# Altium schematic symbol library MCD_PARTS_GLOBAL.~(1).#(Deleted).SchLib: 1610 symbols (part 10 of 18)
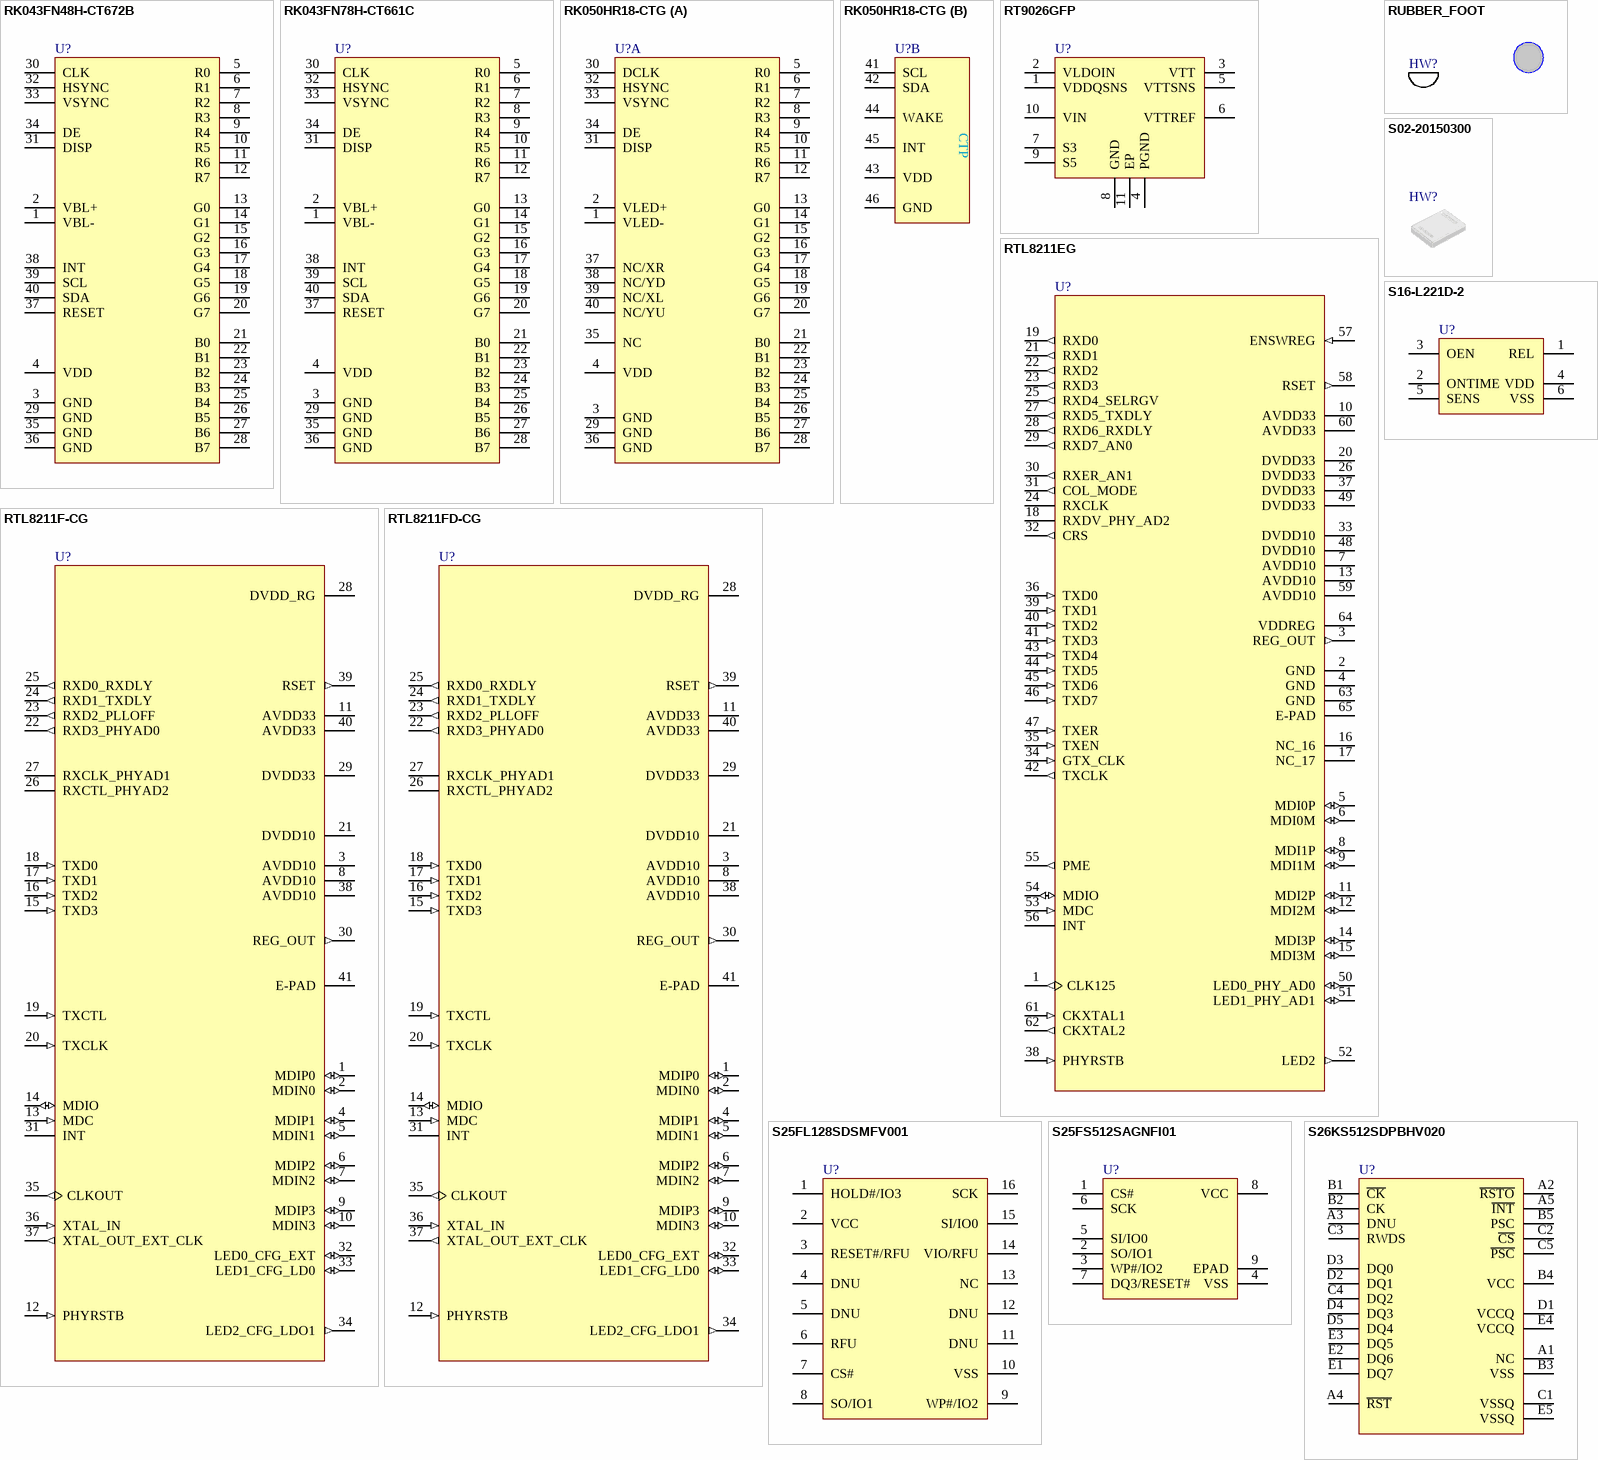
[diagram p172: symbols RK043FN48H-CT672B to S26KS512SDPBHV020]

## RTL8211F-CG
designator U?
pins: 1 MDIP0 (io), 2 MDIN0 (io), 3 AVDD10 (power), 4 MDIP1 (io), 5 MDIN1 (io), 6 MDIP2 (io), 7 MDIN2 (io), 8 AVDD10 (power), 9 MDIP3 (io), 10 MDIN3 (io), 11 AVDD33 (power), 12 PHYRSTB (in), 13 MDC (in), 14 MDIO (io), 15 TXD3 (in), 16 TXD2 (in), 17 TXD1 (in), 18 TXD0 (in), 19 TXCTL (in), 20 TXCLK (in), 21 DVDD10 (power), 22 RXD3_PHYAD0 (out), 23 RXD2_PLLOFF (out), 24 RXD1_TXDLY (out), 25 RXD0_RXDLY (out), 26 RXCTL_PHYAD2, 27 RXCLK_PHYAD1, 28 DVDD_RG (power), 29 DVDD33 (power), 30 REG_OUT (out), 31 INT, 32 LED0_CFG_EXT (io), 33 LED1_CFG_LD0 (io), 34 LED2_CFG_LDO1 (out), 35 CLKOUT (out), 36 XTAL_IN (in), 37 XTAL_OUT_EXT_CLK (out), 38 AVDD10 (power), 39 RSET (out), 40 AVDD33 (power), 41 E-PAD (power)

## RTL8211FD-CG
designator U?
pins: 1 MDIP0 (io), 2 MDIN0 (io), 3 AVDD10 (power), 4 MDIP1 (io), 5 MDIN1 (io), 6 MDIP2 (io), 7 MDIN2 (io), 8 AVDD10 (power), 9 MDIP3 (io), 10 MDIN3 (io), 11 AVDD33 (power), 12 PHYRSTB (in), 13 MDC (in), 14 MDIO (io), 15 TXD3 (in), 16 TXD2 (in), 17 TXD1 (in), 18 TXD0 (in), 19 TXCTL (in), 20 TXCLK (in), 21 DVDD10 (power), 22 RXD3_PHYAD0 (out), 23 RXD2_PLLOFF (out), 24 RXD1_TXDLY (out), 25 RXD0_RXDLY (out), 26 RXCTL_PHYAD2, 27 RXCLK_PHYAD1, 28 DVDD_RG (power), 29 DVDD33 (power), 30 REG_OUT (out), 31 INT, 32 LED0_CFG_EXT (io), 33 LED1_CFG_LD0 (io), 34 LED2_CFG_LDO1 (out), 35 CLKOUT (out), 36 XTAL_IN (in), 37 XTAL_OUT_EXT_CLK (out), 38 AVDD10 (power), 39 RSET (out), 40 AVDD33 (power), 41 E-PAD (power)

## RUBBER_FOOT
designator HW?

## S02-20150300
designator HW?

## S16-L221D-2
designator U?
pins: 1 REL, 2 ONTIME, 3 OEN, 4 VDD, 5 SENS, 6 VSS

## S25FL128SDSMFV001
designator U?
pins: 1 HOLD#/IO3, 2 VCC, 3 RESET#/RFU, 4 DNU, 5 DNU, 6 RFU, 7 CS#, 8 SO/IO1, 9 WP#/IO2, 10 VSS, 11 DNU, 12 DNU, 13 NC, 14 VIO/RFU, 15 SI/IO0, 16 SCK

## S25FS512SAGNFI01
designator U?
pins: 1 CS#, 2 SO/IO1, 3 WP#/IO2, 4 VSS, 5 SI/IO0, 6 SCK, 7 DQ3/RESET#, 8 VCC, 9 EPAD

## S26KS512SDPBHV020
designator U?
pins: A1 NC, A2 ~{RSTO}, A3 DNU, A4 ~{RST}, A5 ~{INT}, B1 ~{CK}, B2 CK, B3 VSS, B4 VCC, B5 PSC, C1 VSSQ, C2 ~{CS}, C3 RWDS, C4 DQ2, C5 ~{PSC}, D1 VCCQ, D2 DQ1, D3 DQ0, D4 DQ3, D5 DQ4, E1 DQ7, E2 DQ6, E3 DQ5, E4 VCCQ, E5 VSSQ

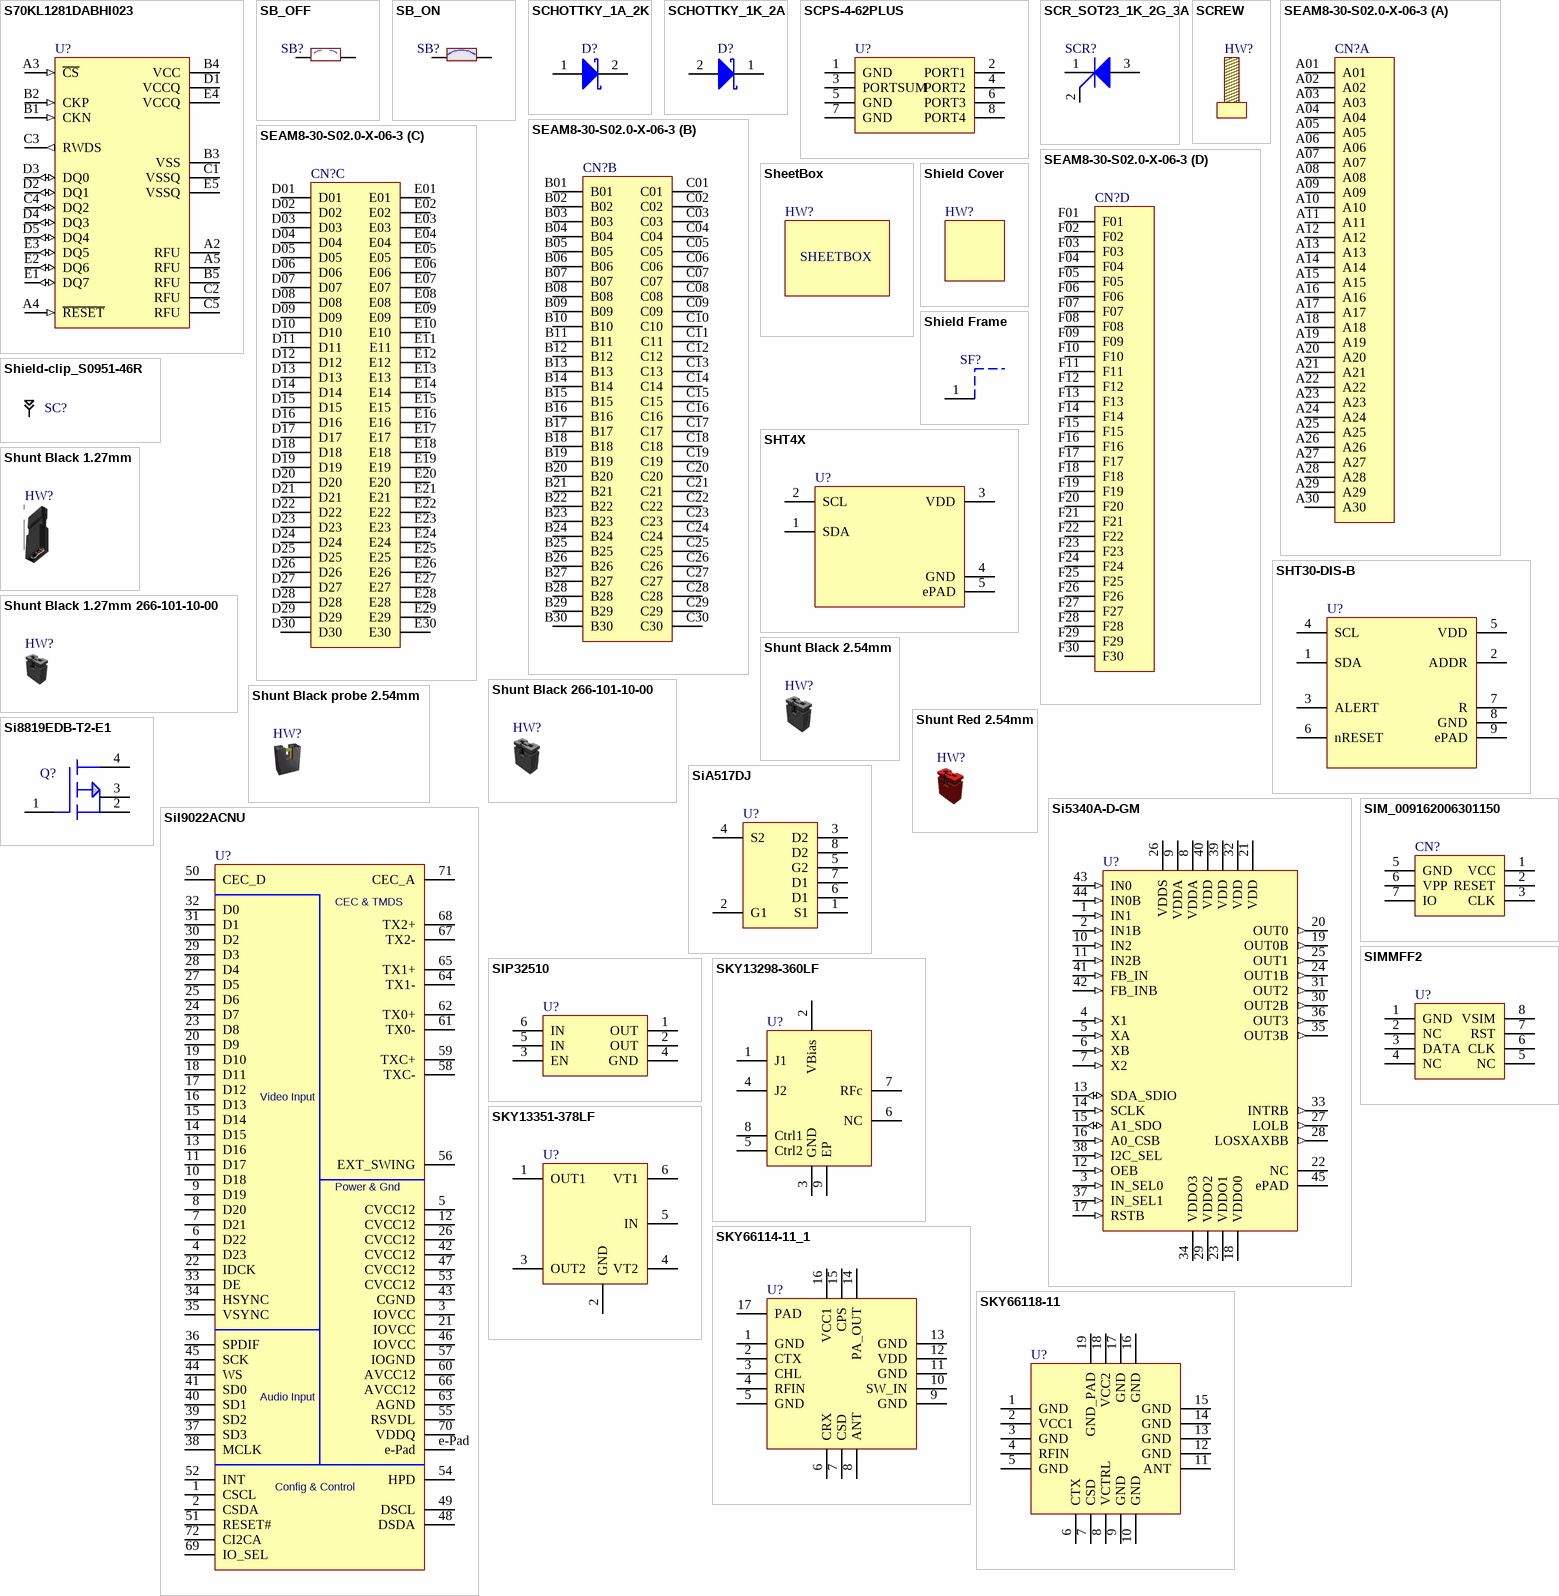
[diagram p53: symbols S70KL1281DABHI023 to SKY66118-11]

## S70KL1281DABHI023
designator U?
pins: A2 RFU (power), A3 ~{CS} (in), A4 ~{RESET} (in), A5 RFU (power), B1 CKN (in), B2 CKP (in), B3 VSS (power), B4 VCC (power), B5 RFU (power), C1 VSSQ (power), C2 RFU (power), C3 RWDS (out), C4 DQ2 (io), C5 RFU (power), D1 VCCQ (power), D2 DQ1 (io), D3 DQ0 (io), D4 DQ3 (io), D5 DQ4 (io), E1 DQ7 (io), E2 DQ6 (io), E3 DQ5 (io), E4 VCCQ (power), E5 VSSQ (power)

## SB_OFF
designator SB?
pins: 1, 2

## SB_ON
designator SB?
pins: 1, 2

## SCHOTTKY_1A_2K
designator D?
pins: 1 A, 2 K

## SCHOTTKY_1K_2A
designator D?
pins: 1 K, 2 A

## SCPS-4-62PLUS
designator U?
pins: 1 GND, 2 PORT1, 3 PORTSUM, 4 PORT2, 5 GND, 6 PORT3, 7 GND, 8 PORT4

## SCR_SOT23_1K_2G_3A
designator SCR?
pins: 1 K, 2 G, 3 A

## SCREW
designator HW?  (mechanical)

## SEAM8-30-S02.0-X-06-3
designator CN?
part A pins: A01, A02, A03, A04, A05, A06, A07, A08, A09, A10, A11, A12, A13, A14, A15, A16, A17, A18, A19, A20, A21, A22, A23, A24, A25, A26, A27, A28, A29, A30
part B pins: B01, B02, B03, B04, B05, B06, B07, B08, B09, B10, B11, B12, B13, B14, B15, B16, B17, B18, B19, B20, B21, B22, B23, B24, B25, B26, B27, B28, B29, B30, C01, C02, C03, C04, C05, C06, C07, C08, C09, C10, C11, C12, C13, C14, C15, C16, C17, C18, C19, C20, C21, C22, C23, C24, C25, C26, C27, C28, C29, C30
part C pins: D01, D02, D03, D04, D05, D06, D07, D08, D09, D10, D11, D12, D13, D14, D15, D16, D17, D18, D19, D20, D21, D22, D23, D24, D25, D26, D27, D28, D29, D30, E01, E02, E03, E04, E05, E06, E07, E08, E09, E10, E11, E12, E13, E14, E15, E16, E17, E18, E19, E20, E21, E22, E23, E24, E25, E26, E27, E28, E29, E30
part D pins: F01, F02, F03, F04, F05, F06, F07, F08, F09, F10, F11, F12, F13, F14, F15, F16, F17, F18, F19, F20, F21, F22, F23, F24, F25, F26, F27, F28, F29, F30

## SheetBox
designator HW?  (no BOM)

## Shield Cover
designator HW?

## Shield Frame
designator SF?
pins: 1

## Shield-clip_S0951-46R
designator SC?
pins: 1

## SHT4X
designator U?
pins: 1 SDA, 2 SCL, 3 VDD, 4 GND, 5 ePAD

## SHT30-DIS-B
designator U?
pins: 1 SDA, 2 ADDR, 3 ALERT, 4 SCL, 5 VDD, 6 nRESET, 7 R, 8 GND, 9 ePAD

## Shunt Black 1.27mm
designator HW?  (mechanical)

## Shunt Black 1.27mm 266-101-10-00
designator HW?  (mechanical)

## Shunt Black 2.54mm
designator HW?  (mechanical)

## Shunt Black 266-101-10-00
designator HW?  (mechanical)

## Shunt Black probe 2.54mm
designator HW?  (mechanical)

## Shunt Red 2.54mm
designator HW?  (mechanical)

## Si5340A-D-GM
designator U?
pins: 1 IN1 (in), 2 IN1B (in), 3 IN_SEL0 (in), 4 X1 (in), 5 XA (in), 6 XB (in), 7 X2 (in), 8 VDDA (power), 9 VDDA (power), 10 IN2 (in), 11 IN2B (in), 12 OEB (in), 13 SDA_SDIO (io), 14 SCLK (in), 15 A1_SDO (io), 16 A0_CSB (in), 17 RSTB (in), 18 VDDO0 (power), 19 OUT0B (out), 20 OUT0 (out), 21 VDD (power), 22 NC, 23 VDDO1 (power), 24 OUT1B (out), 25 OUT1 (out), 26 VDDS (power), 27 LOLB (out), 28 LOSXAXBB (out), 29 VDDO2 (power), 30 OUT2B (out), 31 OUT2 (out), 32 VDD (power), 33 INTRB (out), 34 VDDO3 (power), 35 OUT3B (out), 36 OUT3 (out), 37 IN_SEL1 (in), 38 I2C_SEL (in), 39 VDD (power), 40 VDD (power), 41 FB_IN (in), 42 FB_INB (in), 43 IN0 (in), 44 IN0B (in), 45 ePAD (power)

## Si8819EDB-T2-E1
designator Q?
pins: 1 G, 2 S, 3 S, 4 D

## SiA517DJ
designator U?
pins: 1 S1, 2 G1, 3 D2, 4 S2, 5 G2, 6 D1, 7 D1, 8 D2

## SiI9022ACNU
designator U?
pins: 1 CSCL, 2 CSDA, 3 IOVCC (power), 4 D23, 5 CVCC12 (power), 6 D22, 7 D21, 8 D20, 9 D19, 10 D18, 11 D17, 12 CVCC12 (power), 13 D16, 14 D15, 15 D14, 16 D13, 17 D12, 18 D11, 19 D10, 20 D9, 21 IOVCC (power), 22 IDCK, 23 D8, 24 D7, 25 D6, 26 CVCC12 (power), 27 D5, 28 D4, 29 D3, 30 D2, 31 D1, 32 D0, 33 DE, 34 HSYNC, 35 VSYNC, 36 SPDIF, 37 SD3, 38 MCLK, 39 SD2, 40 SD1, 41 SD0, 42 CVCC12 (power), 43 CGND (power), 44 WS, 45 SCK, 46 IOVCC (power), 47 CVCC12 (power), 48 DSDA, 49 DSCL, 50 CEC_D, 51 RESET#, 52 INT, 53 CVCC12 (power), 54 HPD, 55 RSVDL (power), 56 EXT_SWING, 57 IOGND (power), 58 TXC-, 59 TXC+, 60 AVCC12 (power), 61 TX0-, 62 TX0+, 63 AGND (power), 64 TX1-, 65 TX1+, 66 AVCC12 (power), 67 TX2-, 68 TX2+, 69 IO_SEL, 70 VDDQ (power), 71 CEC_A, 72 CI2CA, e-Pad (power)

## SIM_009162006301150
designator CN?
pins: 1 VCC, 2 RESET, 3 CLK, 5 GND, 6 VPP, 7 IO

## SIMMFF2
designator U?
pins: 1 GND, 2 NC, 3 DATA, 4 NC, 5 NC, 6 CLK, 7 RST, 8 VSIM

## SIP32510
designator U?
pins: 1 OUT, 2 OUT, 3 EN, 4 GND, 5 IN, 6 IN

## SKY13298-360LF
designator U?
pins: 1 J1, 2 VBias, 3 GND, 4 J2, 5 Ctrl2, 6 NC, 7 RFc, 8 Ctrl1, 9 EP

## SKY13351-378LF
designator U?
pins: 1 OUT1, 2 GND, 3 OUT2, 4 VT2, 5 IN, 6 VT1

## SKY66114-11_1
designator U?
pins: 1 GND, 2 CTX, 3 CHL, 4 RFIN, 5 GND, 6 CRX, 7 CSD, 8 ANT, 9 GND, 10 SW_IN, 11 GND, 12 VDD, 13 GND, 14 PA_OUT, 15 CPS, 16 VCC1, 17 PAD

## SKY66118-11
designator U?
pins: 1 GND, 2 VCC1, 3 GND, 4 RFIN, 5 GND, 6 CTX, 7 CSD, 8 VCTRL, 9 GND, 10 GND, 11 ANT, 12 GND, 13 GND, 14 GND, 15 GND, 16 GND, 17 GND, 18 VCC2, 19 GND_PAD

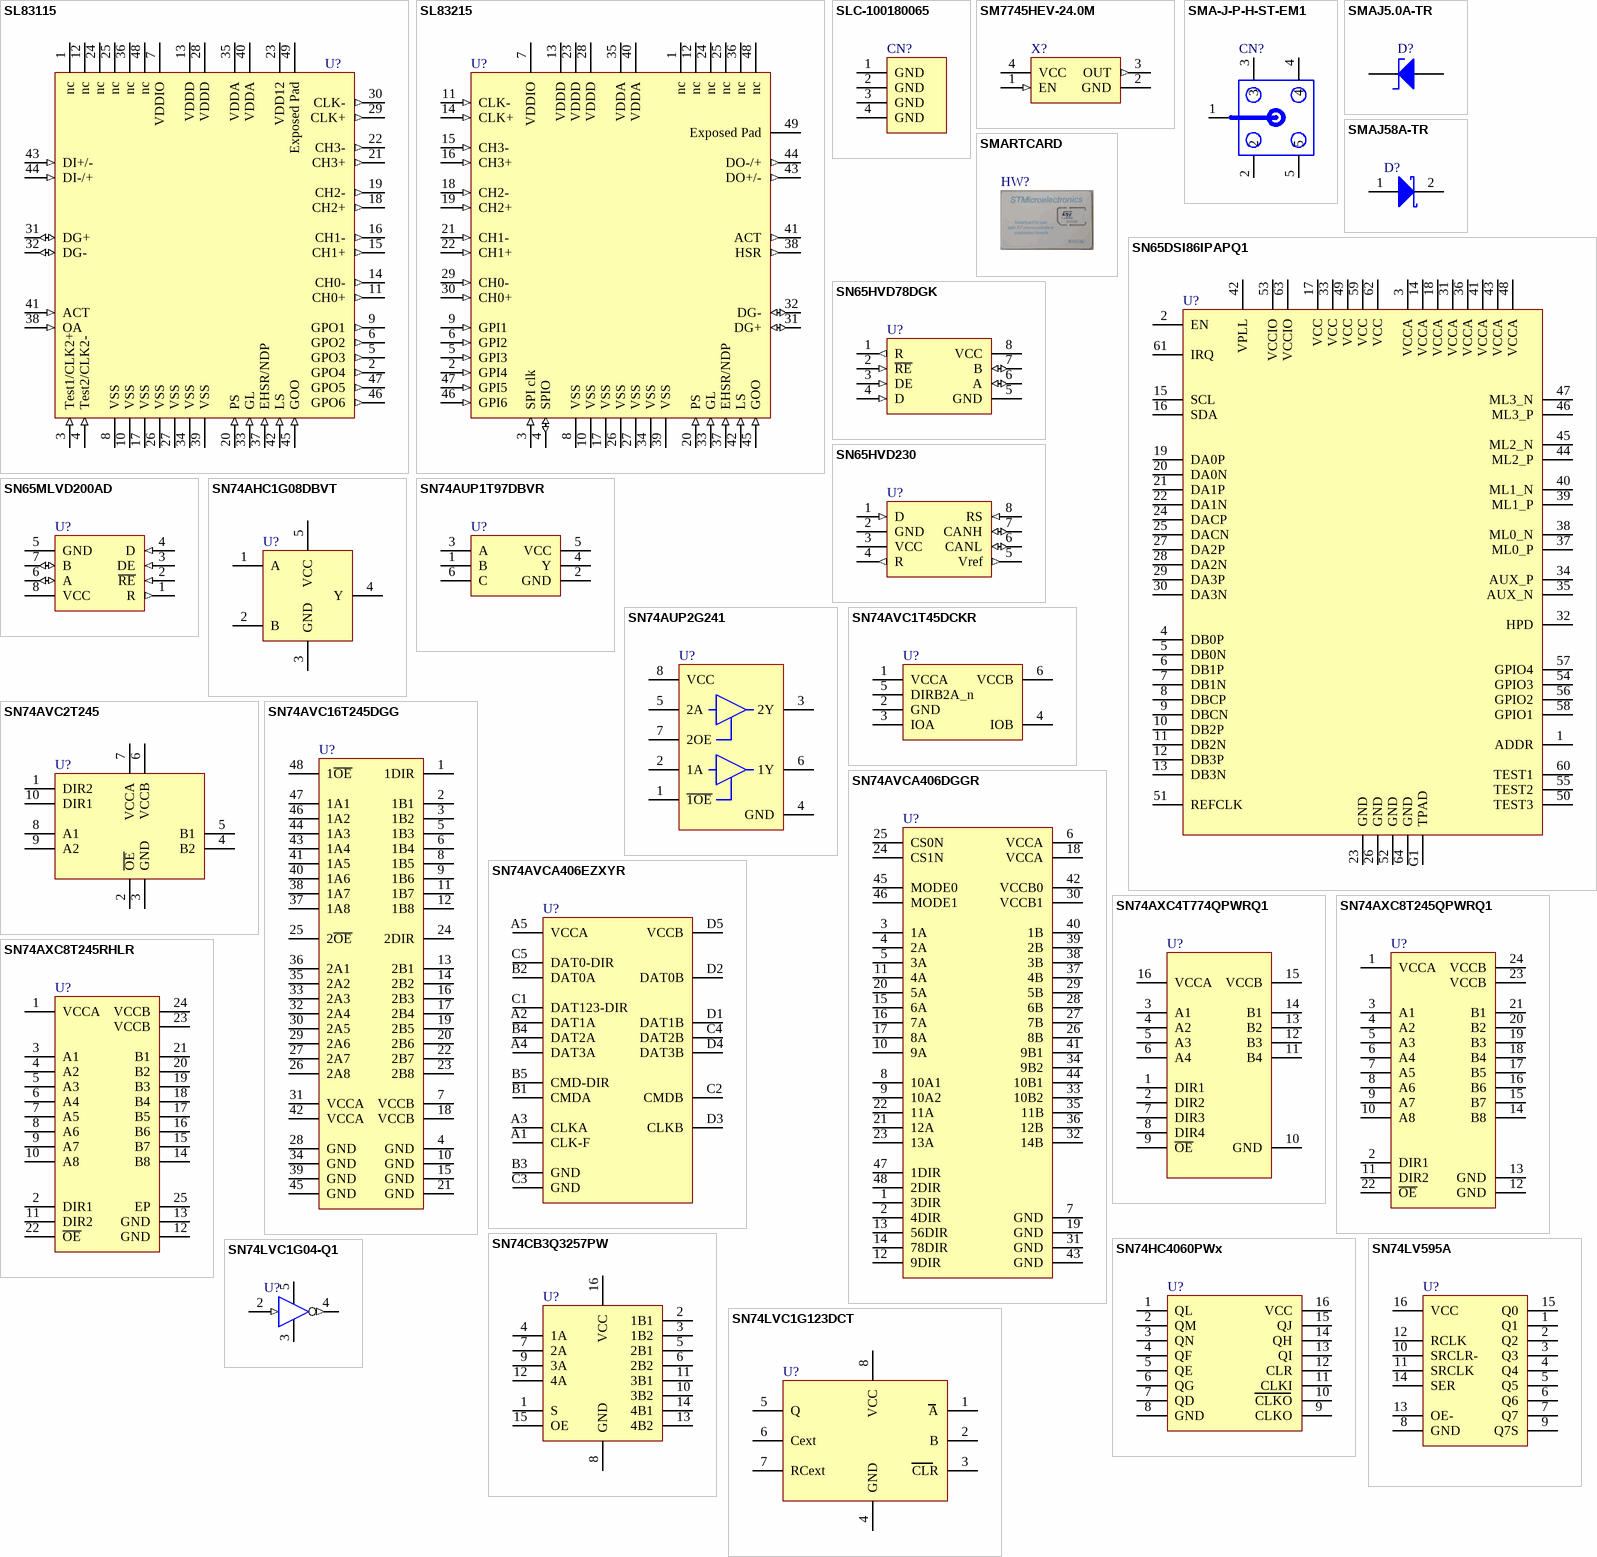
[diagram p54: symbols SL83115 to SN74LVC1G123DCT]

## SL83115
designator U?
pins: 1 nc, 2 GPO4 (out) "General Purpose output 4", 3 Test1/CLK2+ (in) "LS = open: CLK2+. Otherwise, Test pads for internal use only. For correct opration, must be connected to VDDD or VSS", 4 Test2/CLK2- (in) "LS = open: CLK2-. Otherwise, Test pads for internal use only. For correct opration, must be connected to VDDD or VSS", 5 GPO3 (out) "General Purpose output 3", 6 GPO2 (out) "General Purpose output 2", 7 VDDIO (power) "Power supply for GPIO", 8 VSS (power) "Ground", 9 GPO1 (out) "General Purpose output 1", 10 VSS (power) "Ground", 11 CH0+ (out) "Positive differential data output 0", 12 nc, 13 VDDD (power) "Power supply 1.5V", 14 CH0- (out) "Negative differential data output 0", 15 CH1+ (out) "Positive differential data output 1", 16 CH1- (out) "Negative differential data output 1", 17 VSS (power) "Ground", 18 CH2+ (out) "Positive differential data output 2", 19 CH2- (out) "Negative differential data output 2", 20 PS (in) "D0+ and DO- polarity order select", 21 CH3+ (out) "Positive differential data output 3", 22 CH3- (out) "Negative differential data output 3", 23 VDD12 (power) "Power supply 1.2V", 24 nc, 25 nc, 26 VSS (power) "Ground", 27 VSS (power) "Ground", 28 VDDD (power) "Power supply 1.5V", 29 CLK+ (out) "Positive differential clock output", 30 CLK- (out) "Negative differential clock output", 31 DG+ (io) "Positive port of bi-directional galvanic link (when GL=1)", 32 DG- (io) "Negative port of bi-directional galvanic link (when GL=1)", 33 GL (in) "Enables galvanic interface for D-PHY LP operation", 34 VSS (power) "Ground", 35 VDDA (power) "Power supply 1.5V", 36 nc, 37 EHSR/NDP (in) "Enable HSR when =1 and enable non D-PHY mode when open", 38 OA (in) "Normal differential swing amplitude at outputs when OA=0. Half when OA=1.", 39 VSS (power) "Ground", 40 VDDA (power) "Power supply 1.5V", 41 ACT (in) "Activation signal input", 42 LS (in) "Lane Select. =1 only data lanes 0 and 1 may be used. =0, all data lanes may be used", 43 DI+/- (in) "High speed positive (PS=0) or negative (PS=1) differential data input", 44 DI-/+ (in) "High speed negative (PS=0) or positive (PS=1) differential data input", 45 GOO (in) "GPI Over Optical. =1 only GPI1, 3 and 5 are transported. =open, all 6 GPI are transported. =0, no GPI are transported over optical link", 46 GPO6 (out) "General Purpose output 6", 47 GPO5 (out) "General Purpose output 5", 48 nc, 49 Exposed Pad

## SL83215
designator U?
pins: 1 nc, 2 GPI4 (in) "General Purpose Input 4", 3 SPI clk (in) "Test pads for internal use only. For correct opration, must be connected to VDDD or VSS", 4 SPIO (io) "Test pads for internal use only. For correct opration, must be connected to VDDD or VSS", 5 GPI3 (in) "General Purpose Input 3", 6 GPI2 (in) "General Purpose Input 2", 7 VDDIO (power) "Power supply for GPIO", 8 VSS (power) "Ground", 9 GPI1 (in) "General Purpose Input 1", 10 VSS (power) "Ground", 11 CLK- (in) "Negative differential clock input", 12 nc, 13 VDDD (power) "Power supply 1.5V", 14 CLK+ (in) "Positive differential clock input", 15 CH3- (in) "Negative differential data input 3", 16 CH3+ (in) "Positive differential data input 3", 17 VSS (power) "Ground", 18 CH2- (in) "Negative differential data input 2", 19 CH2+ (in) "Positive differential data input 2", 20 PS (in) "D0+ and DO- polarity order select", 21 CH1- (in) "Negative differential data input 1", 22 CH1+ (in) "Positive differential data input 1", 23 VDDD (power) "Power supply 1.5V", 24 nc, 25 nc, 26 VSS (power) "Ground", 27 VSS (power) "Ground", 28 VDDD (power) "Power supply 1.5V", 29 CH0- (in) "Negative differential data input 0", 30 CH0+ (in) "Positive differential data input 0", 31 DG+ (io) "Positive port of bi-directional galvanic link (when GL=1)", 32 DG- (io) "Negative port of bi-directional galvanic link (when GL=1)", 33 GL (in) "Enables galvanic interface for D-PHY LP operation", 34 VSS (power) "Ground", 35 VDDA (power) "Power supply 1.5V", 36 nc, 37 EHSR/NDP (in) "Enable HSR when =1 and enable non D-PHY mode when open", 38 HSR (out) "High Speed Ready signal output when EHSR=1", 39 VSS (power) "Ground", 40 VDDA (power) "Power supply 1.5V", 41 ACT (out) "Activation signal output", 42 LS (in) "Lane Select. =1 only data lanes 0 and 1 may be used. =0, all data lanes may be used", 43 DO+/- (out) "High speed positive (PS=0) or negative (PS=1) differential data output", 44 DO-/+ (out) "High speed negative (PS=0) or positive (PS=1) differential data output", 45 GOO (in) "GPI Over Optical. =1 only GPI1, 3 and 5 are transported. =open, all 6 GPI are transported. =0, no GPI are transported over optical link", 46 GPI6 (in) "General Purpose Input 6", 47 GPI5 (in) "General Purpose Input 5", 48 nc, 49 Exposed Pad

## SLC-100180065
designator CN?
pins: 1 GND, 2 GND, 3 GND, 4 GND

## SM7745HEV-24.0M
designator X?
pins: 1 EN (in), 2 GND, 3 OUT (out), 4 VCC

## SMA-J-P-H-ST-EM1
designator CN?
pins: 1, 2, 3, 4, 5

## SMAJ5.0A-TR
designator D?
pins: 1 A, 2 K

## SMAJ58A-TR
designator D?
pins: 1 A, 2 K

## SMARTCARD
designator HW?  (mechanical)

## SN65DSI86IPAPQ1
designator U?
pins: 1 ADDR, 2 EN, 3 VCCA, 4 DB0P, 5 DB0N, 6 DB1P, 7 DB1N, 8 DBCP, 9 DBCN, 10 DB2P, 11 DB2N, 12 DB3P, 13 DB3N, 14 VCCA, 15 SCL, 16 SDA, 17 VCC, 18 VCCA, 19 DA0P, 20 DA0N, 21 DA1P, 22 DA1N, 23 GND, 24 DACP, 25 DACN, 26 GND, 27 DA2P, 28 DA2N, 29 DA3P, 30 DA3N, 31 VCCA, 32 HPD, 33 VCC, 34 AUX_P, 35 AUX_N, 36 VCCA, 37 ML0_P, 38 ML0_N, 39 ML1_P, 40 ML1_N, 41 VCCA, 42 VPLL, 43 VCCA, 44 ML2_P, 45 ML2_N, 46 ML3_P, 47 ML3_N, 48 VCCA, 49 VCC, 50 TEST3, 51 REFCLK, 52 GND, 53 VCCIO, 54 GPIO3, 55 TEST2, 56 GPIO2, 57 GPIO4, 58 GPIO1, 59 VCC, 60 TEST1, 61 IRQ, 62 VCC, 63 VCCIO, 64 GND, G1 TPAD

## SN65HVD78DGK
designator U?
pins: 1 R (out), 2 ~{RE} (in), 3 DE (in), 4 D (in), 5 GND (power), 6 A (io), 7 B (io), 8 VCC (power)

## SN65HVD230
designator U?
pins: 1 D (in), 2 GND (power), 3 VCC (power), 4 R (out), 5 Vref (out), 6 CANL (io), 7 CANH (io), 8 RS (in)

## SN65MLVD200AD
designator U?
pins: 1 R (out), 2 ~{RE} (in), 3 DE (in), 4 D (in), 5 GND, 6 A (io), 7 B (io), 8 VCC

## SN74AHC1G08DBVT
designator U?
pins: 1 A, 2 B, 3 GND, 4 Y, 5 VCC

## SN74AUP1T97DBVR
designator U?
pins: 1 B, 2 GND, 3 A, 4 Y, 5 VCC, 6 C

## SN74AUP2G241
designator U?
pins: 1 ~{1OE}, 2 1A, 3 2Y, 4 GND, 5 2A, 6 1Y, 7 2OE, 8 VCC

## SN74AVC1T45DCKR
designator U?
pins: 1 VCCA, 2 GND, 3 IOA, 4 IOB, 5 DIRB2A_n, 6 VCCB

## SN74AVC2T245
designator U?
pins: 1 DIR2, 2 ~{OE}, 3 GND, 4 B2, 5 B1, 6 VCCB, 7 VCCA, 8 A1, 9 A2, 10 DIR1

## SN74AVC16T245DGG
designator U?
pins: 1 1DIR, 2 1B1, 3 1B2, 4 GND, 5 1B3, 6 1B4, 7 VCCB, 8 1B5, 9 1B6, 10 GND, 11 1B7, 12 1B8, 13 2B1, 14 2B2, 15 GND, 16 2B3, 17 2B4, 18 VCCB, 19 2B5, 20 2B6, 21 GND, 22 2B7, 23 2B8, 24 2DIR, 25 2~{OE}, 26 2A8, 27 2A7, 28 GND, 29 2A6, 30 2A5, 31 VCCA, 32 2A4, 33 2A3, 34 GND, 35 2A2, 36 2A1, 37 1A8, 38 1A7, 39 GND, 40 1A6, 41 1A5, 42 VCCA, 43 1A4, 44 1A3, 45 GND, 46 1A2, 47 1A1, 48 1~{OE}

## SN74AVCA406DGGR
designator U?
pins: 1 3DIR, 2 4DIR, 3 1A, 4 2A, 5 3A, 6 VCCA, 7 GND, 8 10A1, 9 10A2, 10 9A, 11 4A, 12 9DIR, 13 56DIR, 14 78DIR, 15 6A, 16 7A, 17 8A, 18 VCCA, 19 GND, 20 5A, 21 12A, 22 11A, 23 13A, 24 CS1N, 25 CS0N, 26 8B, 27 7B, 28 6B, 29 5B, 30 VCCB1, 31 GND, 32 14B, 33 10B2, 34 9B2, 35 11B, 36 12B, 37 4B, 38 3B, 39 2B, 40 1B, 41 9B1, 42 VCCB0, 43 GND, 44 10B1, 45 MODE0, 46 MODE1, 47 1DIR, 48 2DIR

## SN74AVCA406EZXYR
designator U?
pins: A1 CLK-F, A2 DAT1A, A3 CLKA, A4 DAT3A, A5 VCCA, B1 CMDA, B2 DAT0A, B3 GND, B4 DAT2A, B5 CMD-DIR, C1 DAT123-DIR, C2 CMDB, C3 GND, C4 DAT2B, C5 DAT0-DIR, D1 DAT1B, D2 DAT0B, D3 CLKB, D4 DAT3B, D5 VCCB

## SN74AXC4T774QPWRQ1
designator U?
pins: 1 DIR1, 2 DIR2, 3 A1, 4 A2, 5 A3, 6 A4, 7 DIR3, 8 DIR4, 9 ~{OE}, 10 GND, 11 B4, 12 B3, 13 B2, 14 B1, 15 VCCB, 16 VCCA

## SN74AXC8T245QPWRQ1
designator U?
pins: 1 VCCA, 2 DIR1, 3 A1, 4 A2, 5 A3, 6 A4, 7 A5, 8 A6, 9 A7, 10 A8, 11 DIR2, 12 GND, 13 GND, 14 B8, 15 B7, 16 B6, 17 B5, 18 B4, 19 B3, 20 B2, 21 B1, 22 ~{OE}, 23 VCCB, 24 VCCB

## SN74AXC8T245RHLR
designator U?
pins: 1 VCCA, 2 DIR1, 3 A1, 4 A2, 5 A3, 6 A4, 7 A5, 8 A6, 9 A7, 10 A8, 11 DIR2, 12 GND, 13 GND, 14 B8, 15 B7, 16 B6, 17 B5, 18 B4, 19 B3, 20 B2, 21 B1, 22 ~{OE}, 23 VCCB, 24 VCCB, 25 EP

## SN74CB3Q3257PW
designator U?
pins: 1 S, 2 1B1, 3 1B2, 4 1A, 5 2B1, 6 2B2, 7 2A, 8 GND, 9 3A, 10 3B2, 11 3B1, 12 4A, 13 4B2, 14 4B1, 15 OE, 16 VCC

## SN74HC4060PWx
designator U?
pins: 1 QL, 2 QM, 3 QN, 4 QF, 5 QE, 6 QG, 7 QD, 8 GND, 9 CLKO, 10 CLKO, 11 CLKI, 12 CLR, 13 QI, 14 QH, 15 QJ, 16 VCC

## SN74LV595A
designator U?
pins: 1 Q1, 2 Q2, 3 Q3, 4 Q4, 5 Q5, 6 Q6, 7 Q7, 8 GND, 9 Q7S, 10 SRCLR-, 11 SRCLK, 12 RCLK, 13 OE-, 14 SER, 15 Q0, 16 VCC

## SN74LVC1G04-Q1
designator U?
pins: 1 NC hidden, 2 1A (in), 3 GND, 4 1Y (out), 5 VCC

## SN74LVC1G123DCT
designator U?
pins: 1 A, 2 B, 3 CLR, 4 GND, 5 Q, 6 Cext, 7 RCext, 8 VCC

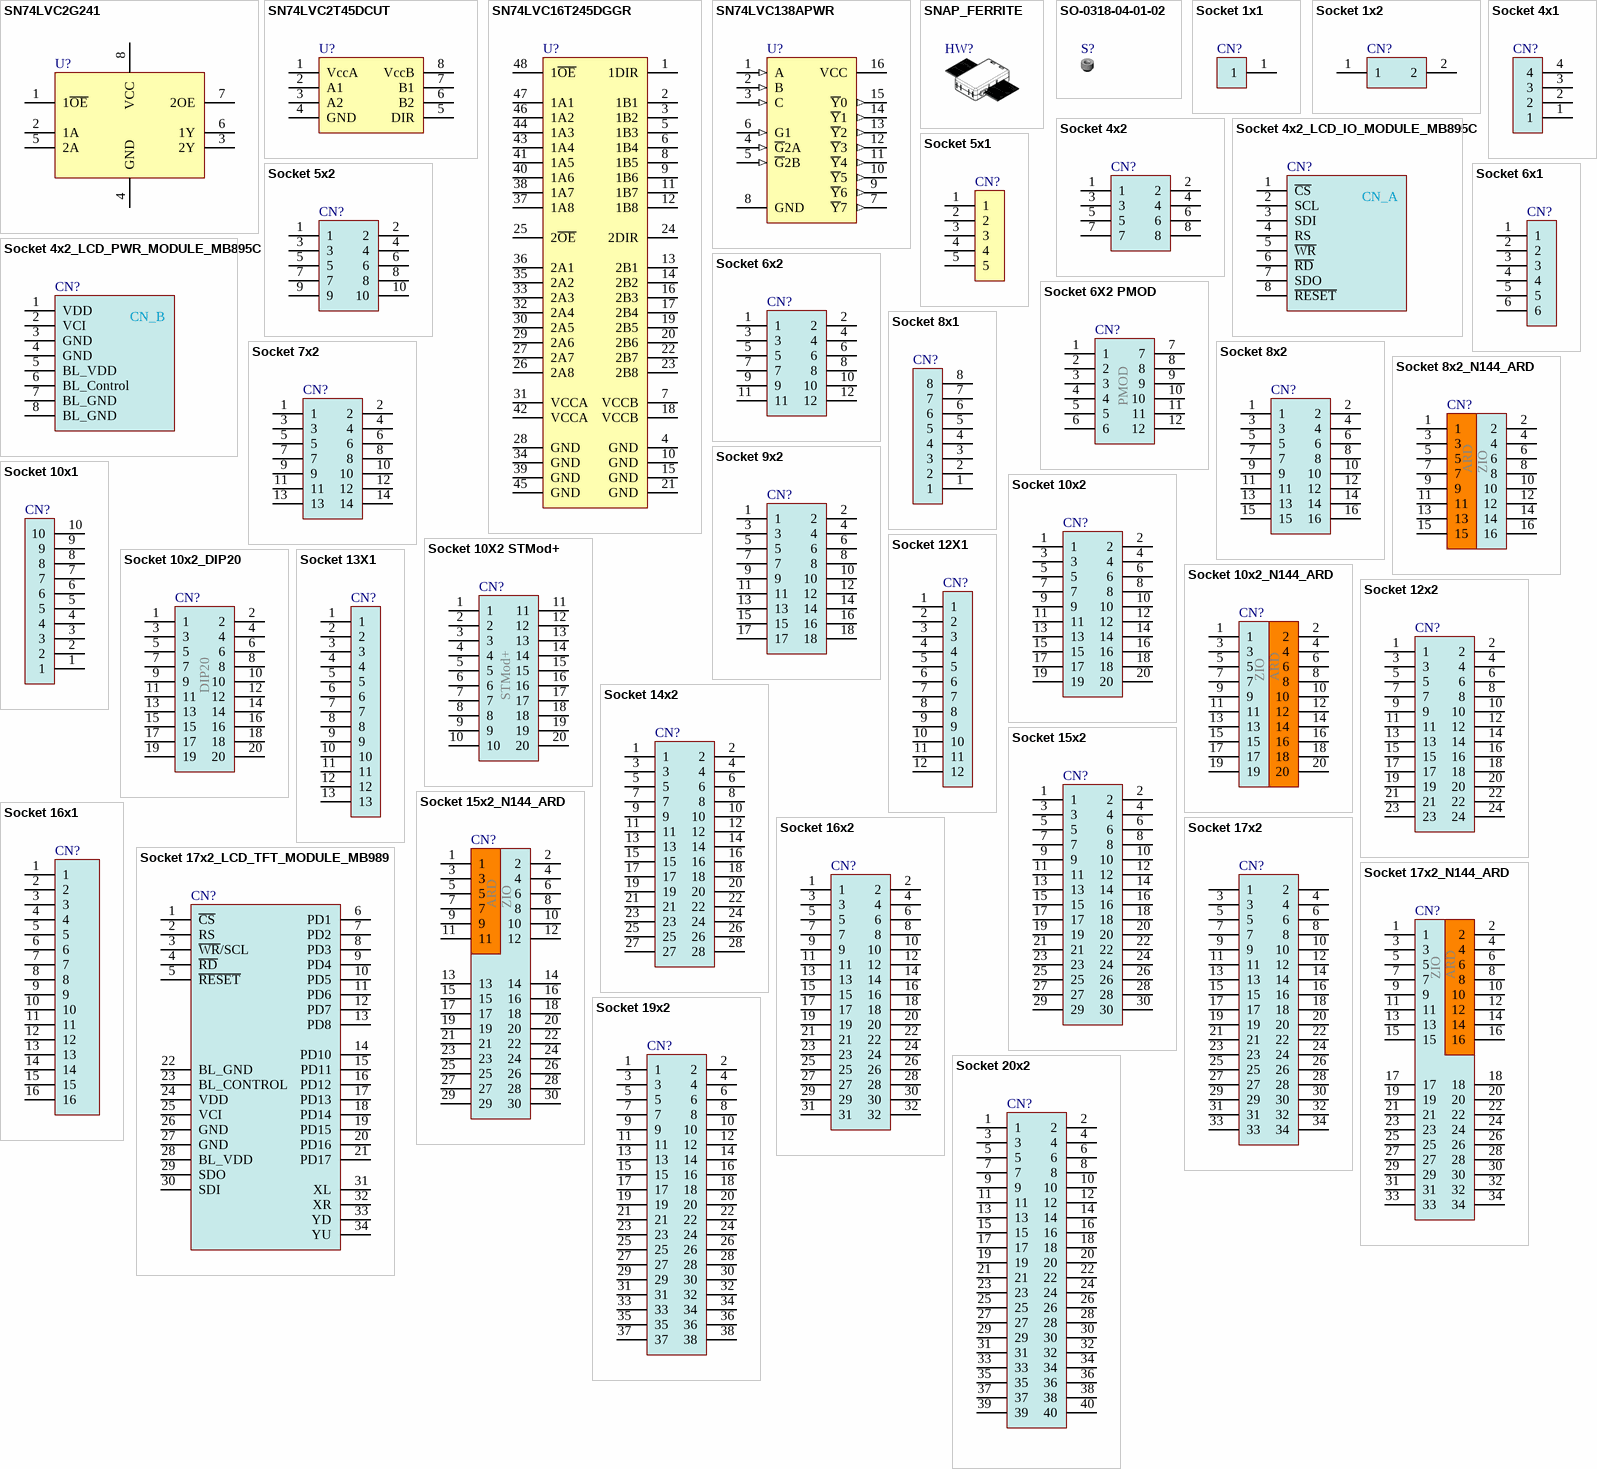
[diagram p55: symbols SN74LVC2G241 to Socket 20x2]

## SN74LVC2G241
designator U?
pins: 1 1~{OE}, 2 1A, 3 2Y, 4 GND, 5 2A, 6 1Y, 7 2OE, 8 VCC

## SN74LVC2T45DCUT
designator U?
pins: 1 VccA (power), 2 A1, 3 A2, 4 GND (power), 5 DIR, 6 B2, 7 B1, 8 VccB (power)

## SN74LVC16T245DGGR
designator U?
pins: 1 1DIR, 2 1B1, 3 1B2, 4 GND, 5 1B3, 6 1B4, 7 VCCB, 8 1B5, 9 1B6, 10 GND, 11 1B7, 12 1B8, 13 2B1, 14 2B2, 15 GND, 16 2B3, 17 2B4, 18 VCCB, 19 2B5, 20 2B6, 21 GND, 22 2B7, 23 2B8, 24 2DIR, 25 2~{OE}, 26 2A8, 27 2A7, 28 GND, 29 2A6, 30 2A5, 31 VCCA, 32 2A4, 33 2A3, 34 GND, 35 2A2, 36 2A1, 37 1A8, 38 1A7, 39 GND, 40 1A6, 41 1A5, 42 VCCA, 43 1A4, 44 1A3, 45 GND, 46 1A2, 47 1A1, 48 1~{OE}
1 alternate drawing of the same symbol

## SN74LVC138APWR
designator U?
pins: 1 A (in), 2 B (in), 3 C (in), 4 ~{G}2A (in), 5 ~{G}2B (in), 6 G1 (in), 7 ~{Y}7 (out), 8 GND (power), 9 ~{Y}6 (out), 10 ~{Y}5 (out), 11 ~{Y}4 (out), 12 ~{Y}3 (out), 13 ~{Y}2 (out), 14 ~{Y}1 (out), 15 ~{Y}0 (out), 16 VCC (power)

## SNAP_FERRITE
designator HW?  (mechanical)

## SO-0318-04-01-02
designator S?

## Socket 1x1
designator CN?
pins: 1

## Socket 1x2
designator CN?
pins: 1, 2

## Socket 4x1
designator CN?
pins: 1, 2, 3, 4

## Socket 4x2
designator CN?
pins: 1, 2, 3, 4, 5, 6, 7, 8

## Socket 4x2_LCD_IO_MODULE_MB895C
designator CN?
pins: 1 ~{CS}, 2 SCL, 3 SDI, 4 RS, 5 ~{WR}, 6 ~{RD}, 7 SDO, 8 ~{RESET}

## Socket 4x2_LCD_PWR_MODULE_MB895C
designator CN?
pins: 1 VDD, 2 VCI, 3 GND, 4 GND, 5 BL_VDD, 6 BL_Control, 7 BL_GND, 8 BL_GND

## Socket 5x1
designator CN?
pins: 1, 2, 3, 4, 5
1 alternate drawing of the same symbol

## Socket 5x2
designator CN?
pins: 1, 2, 3, 4, 5, 6, 7, 8, 9, 10

## Socket 6x1
designator CN?
pins: 1, 2, 3, 4, 5, 6
1 alternate drawing of the same symbol

## Socket 6x2
designator CN?
pins: 1, 2, 3, 4, 5, 6, 7, 8, 9, 10, 11, 12

## Socket 6X2 PMOD
designator CN?
pins: 1, 2, 3, 4, 5, 6, 7, 8, 9, 10, 11, 12

## Socket 7x2
designator CN?
pins: 1, 2, 3, 4, 5, 6, 7, 8, 9, 10, 11, 12, 13, 14

## Socket 8x1
designator CN?
pins: 1, 2, 3, 4, 5, 6, 7, 8
2 alternate drawings of the same symbol

## Socket 8x2
designator CN?
pins: 1, 2, 3, 4, 5, 6, 7, 8, 9, 10, 11, 12, 13, 14, 15, 16

## Socket 8x2_N144_ARD
designator CN?
pins: 1, 2, 3, 4, 5, 6, 7, 8, 9, 10, 11, 12, 13, 14, 15, 16

## Socket 9x2
designator CN?
pins: 1, 2, 3, 4, 5, 6, 7, 8, 9, 10, 11, 12, 13, 14, 15, 16, 17, 18

## Socket 10x1
designator CN?
pins: 1, 2, 3, 4, 5, 6, 7, 8, 9, 10
1 alternate drawing of the same symbol

## Socket 10x2
designator CN?
pins: 1, 2, 3, 4, 5, 6, 7, 8, 9, 10, 11, 12, 13, 14, 15, 16, 17, 18, 19, 20

## Socket 10X2 STMod+
designator CN?
pins: 1, 2, 3, 4, 5, 6, 7, 8, 9, 10, 11, 12, 13, 14, 15, 16, 17, 18, 19, 20

## Socket 10x2_DIP20
designator CN?
pins: 1, 2, 3, 4, 5, 6, 7, 8, 9, 10, 11, 12, 13, 14, 15, 16, 17, 18, 19, 20

## Socket 10x2_N144_ARD
designator CN?
pins: 1, 2, 3, 4, 5, 6, 7, 8, 9, 10, 11, 12, 13, 14, 15, 16, 17, 18, 19, 20

## Socket 12X1
designator CN?
pins: 1, 2, 3, 4, 5, 6, 7, 8, 9, 10, 11, 12

## Socket 12x2
designator CN?
pins: 1, 2, 3, 4, 5, 6, 7, 8, 9, 10, 11, 12, 13, 14, 15, 16, 17, 18, 19, 20, 21, 22, 23, 24

## Socket 13X1
designator CN?
pins: 1, 2, 3, 4, 5, 6, 7, 8, 9, 10, 11, 12, 13

## Socket 14x2
designator CN?
pins: 1, 2, 3, 4, 5, 6, 7, 8, 9, 10, 11, 12, 13, 14, 15, 16, 17, 18, 19, 20, 21, 22, 23, 24, 25, 26, 27, 28

## Socket 15x2
designator CN?
pins: 1, 2, 3, 4, 5, 6, 7, 8, 9, 10, 11, 12, 13, 14, 15, 16, 17, 18, 19, 20, 21, 22, 23, 24, 25, 26, 27, 28, 29, 30

## Socket 15x2_N144_ARD
designator CN?
pins: 1, 2, 3, 4, 5, 6, 7, 8, 9, 10, 11, 12, 13, 14, 15, 16, 17, 18, 19, 20, 21, 22, 23, 24, 25, 26, 27, 28, 29, 30

## Socket 16x1
designator CN?
pins: 1, 2, 3, 4, 5, 6, 7, 8, 9, 10, 11, 12, 13, 14, 15, 16

## Socket 16x2
designator CN?
pins: 1, 2, 3, 4, 5, 6, 7, 8, 9, 10, 11, 12, 13, 14, 15, 16, 17, 18, 19, 20, 21, 22, 23, 24, 25, 26, 27, 28, 29, 30, 31, 32

## Socket 17x2
designator CN?
pins: 1, 2, 3, 4, 5, 6, 7, 8, 9, 10, 11, 12, 13, 14, 15, 16, 17, 18, 19, 20, 21, 22, 23, 24, 25, 26, 27, 28, 29, 30, 31, 32, 33, 34

## Socket 17x2_LCD_TFT_MODULE_MB989
designator CN?
pins: 1 ~{CS}, 2 RS, 3 ~{WR}/SCL, 4 ~{RD}, 5 ~{RESET}, 6 PD1, 7 PD2, 8 PD3, 9 PD4, 10 PD5, 11 PD6, 12 PD7, 13 PD8, 14 PD10, 15 PD11, 16 PD12, 17 PD13, 18 PD14, 19 PD15, 20 PD16, 21 PD17, 22 BL_GND, 23 BL_CONTROL, 24 VDD, 25 VCI, 26 GND, 27 GND, 28 BL_VDD, 29 SDO, 30 SDI, 31 XL, 32 XR, 33 YD, 34 YU

## Socket 17x2_N144_ARD
designator CN?
pins: 1, 2, 3, 4, 5, 6, 7, 8, 9, 10, 11, 12, 13, 14, 15, 16, 17, 18, 19, 20, 21, 22, 23, 24, 25, 26, 27, 28, 29, 30, 31, 32, 33, 34

## Socket 19x2
designator CN?
pins: 1, 2, 3, 4, 5, 6, 7, 8, 9, 10, 11, 12, 13, 14, 15, 16, 17, 18, 19, 20, 21, 22, 23, 24, 25, 26, 27, 28, 29, 30, 31, 32, 33, 34, 35, 36, 37, 38

## Socket 20x2
designator CN?
pins: 1, 2, 3, 4, 5, 6, 7, 8, 9, 10, 11, 12, 13, 14, 15, 16, 17, 18, 19, 20, 21, 22, 23, 24, 25, 26, 27, 28, 29, 30, 31, 32, 33, 34, 35, 36, 37, 38, 39, 40

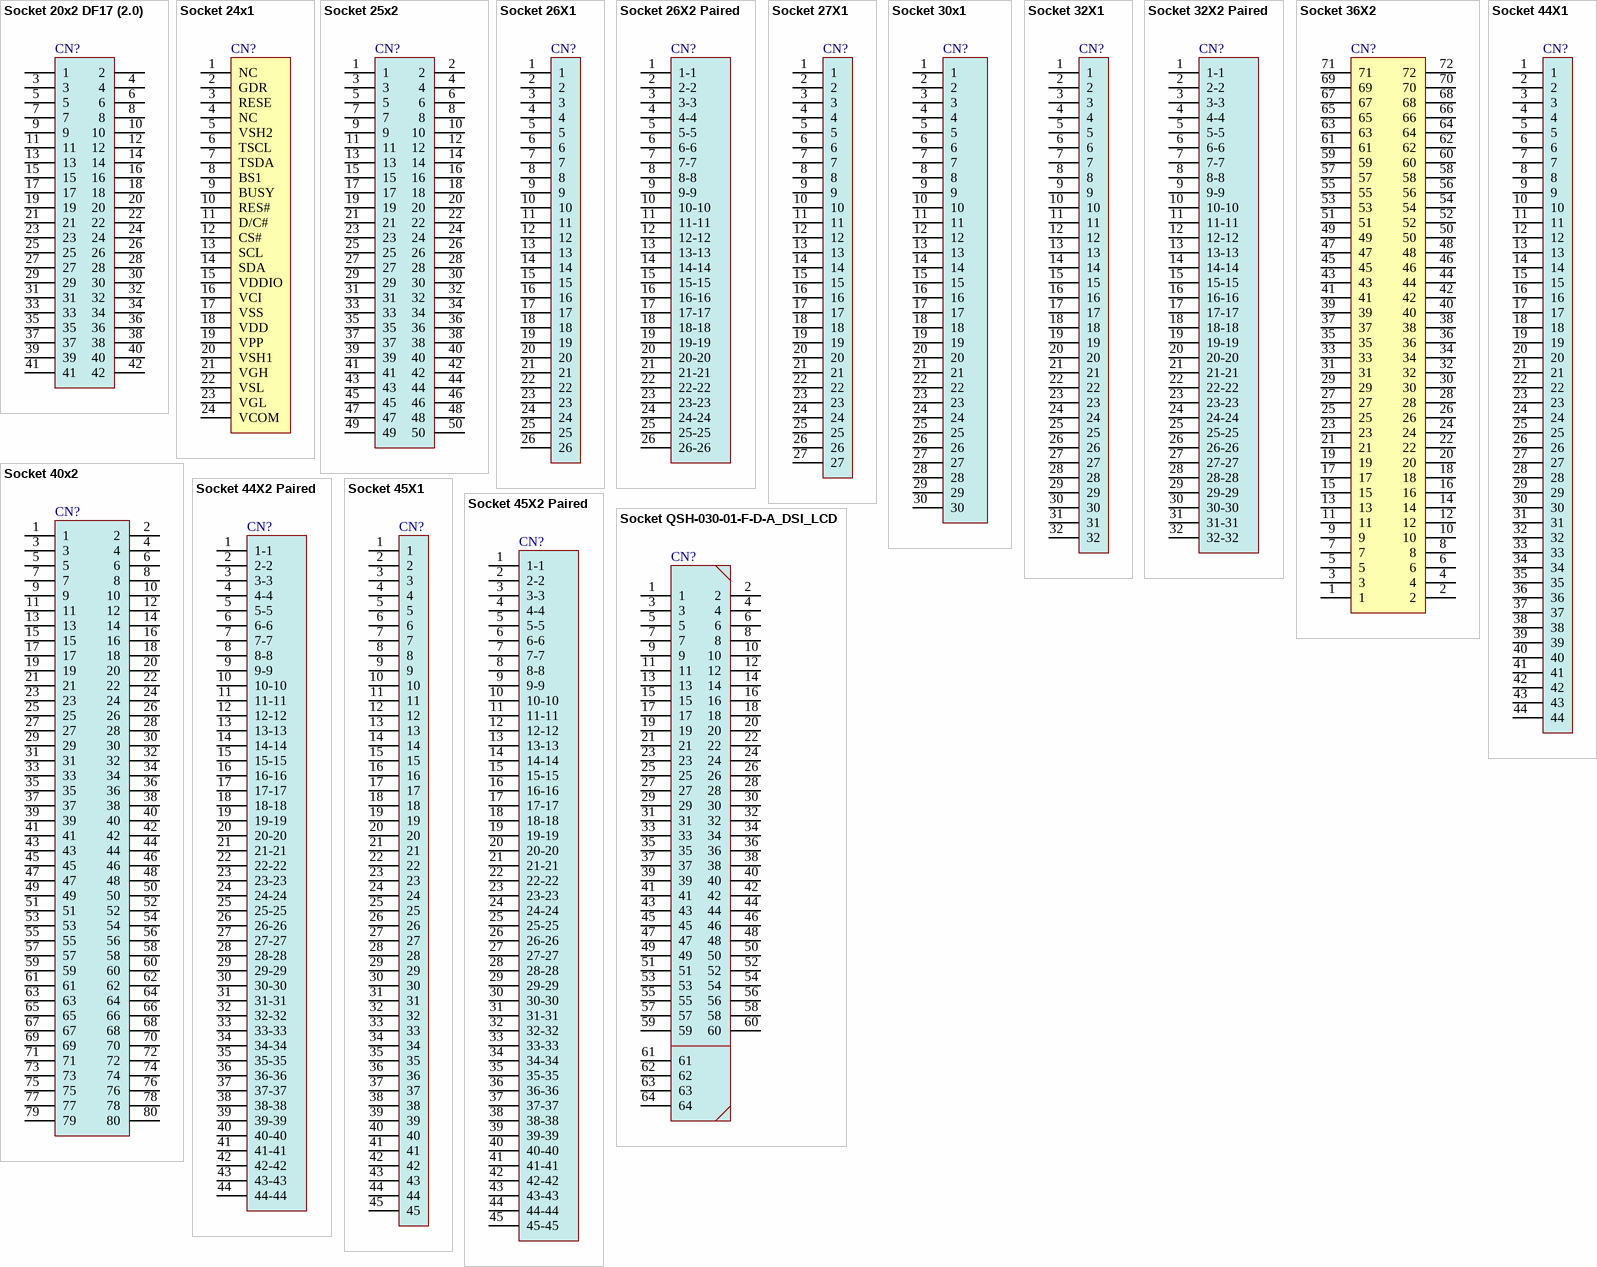
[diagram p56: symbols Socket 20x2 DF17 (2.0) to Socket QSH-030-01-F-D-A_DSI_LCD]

## Socket 20x2 DF17 (2.0)
designator CN?
pins: 1, 2, 3, 4, 5, 6, 7, 8, 9, 10, 11, 12, 13, 14, 15, 16, 17, 18, 19, 20, 21, 22, 23, 24, 25, 26, 27, 28, 29, 30, 31, 32, 33, 34, 35, 36, 37, 38, 39, 40, 41 "METAL 1", 42 "METAL 2"

## Socket 24x1
designator CN?
pins: 1 NC, 2 GDR, 3 RESE, 4 NC, 5 VSH2, 6 TSCL, 7 TSDA, 8 BS1, 9 BUSY, 10 RES#, 11 D/C#, 12 CS#, 13 SCL, 14 SDA, 15 VDDIO, 16 VCI, 17 VSS, 18 VDD, 19 VPP, 20 VSH1, 21 VGH, 22 VSL, 23 VGL, 24 VCOM

## Socket 25x2
designator CN?
An alternate mode is available
pins: 1, 2, 3, 4, 5, 6, 7, 8, 9, 10, 11, 12, 13, 14, 15, 16, 17, 18, 19, 20, 21, 22, 23, 24, 25, 26, 27, 28, 29, 30, 31, 32, 33, 34, 35, 36, 37, 38, 39, 40, 41, 42, 43, 44, 45, 46, 47, 48, 49, 50
2 alternate drawings of the same symbol

## Socket 26X1
designator CN?
pins: 1, 2, 3, 4, 5, 6, 7, 8, 9, 10, 11, 12, 13, 14, 15, 16, 17, 18, 19, 20, 21, 22, 23, 24, 25, 26

## Socket 26X2 Paired
designator CN?
pins: 1 1-1, 2 2-2, 3 3-3, 4 4-4, 5 5-5, 6 6-6, 7 7-7, 8 8-8, 9 9-9, 10 10-10, 11 11-11, 12 12-12, 13 13-13, 14 14-14, 15 15-15, 16 16-16, 17 17-17, 18 18-18, 19 19-19, 20 20-20, 21 21-21, 22 22-22, 23 23-23, 24 24-24, 25 25-25, 26 26-26

## Socket 27X1
designator CN?
pins: 1, 2, 3, 4, 5, 6, 7, 8, 9, 10, 11, 12, 13, 14, 15, 16, 17, 18, 19, 20, 21, 22, 23, 24, 25, 26, 27

## Socket 30x1
designator CN?
pins: 1, 2, 3, 4, 5, 6, 7, 8, 9, 10, 11, 12, 13, 14, 15, 16, 17, 18, 19, 20, 21, 22, 23, 24, 25, 26, 27, 28, 29, 30

## Socket 32X1
designator CN?
pins: 1, 2, 3, 4, 5, 6, 7, 8, 9, 10, 11, 12, 13, 14, 15, 16, 17, 18, 19, 20, 21, 22, 23, 24, 25, 26, 27, 28, 29, 30, 31, 32

## Socket 32X2 Paired
designator CN?
pins: 1 1-1, 2 2-2, 3 3-3, 4 4-4, 5 5-5, 6 6-6, 7 7-7, 8 8-8, 9 9-9, 10 10-10, 11 11-11, 12 12-12, 13 13-13, 14 14-14, 15 15-15, 16 16-16, 17 17-17, 18 18-18, 19 19-19, 20 20-20, 21 21-21, 22 22-22, 23 23-23, 24 24-24, 25 25-25, 26 26-26, 27 27-27, 28 28-28, 29 29-29, 30 30-30, 31 31-31, 32 32-32

## Socket 36X2
designator CN?
pins: 1, 2, 3, 4, 5, 6, 7, 8, 9, 10, 11, 12, 13, 14, 15, 16, 17, 18, 19, 20, 21, 22, 23, 24, 25, 26, 27, 28, 29, 30, 31, 32, 33, 34, 35, 36, 37, 38, 39, 40, 41, 42, 43, 44, 45, 46, 47, 48, 49, 50, 51, 52, 53, 54, 55, 56, 57, 58, 59, 60, 61, 62, 63, 64, 65, 66, 67, 68, 69, 70, 71, 72

## Socket 40x2
designator CN?
pins: 1, 2, 3, 4, 5, 6, 7, 8, 9, 10, 11, 12, 13, 14, 15, 16, 17, 18, 19, 20, 21, 22, 23, 24, 25, 26, 27, 28, 29, 30, 31, 32, 33, 34, 35, 36, 37, 38, 39, 40, 41, 42, 43, 44, 45, 46, 47, 48, 49, 50, 51, 52, 53, 54, 55, 56, 57, 58, 59, 60, 61, 62, 63, 64, 65, 66, 67, 68, 69, 70, 71, 72, 73, 74, 75, 76, 77, 78, 79, 80

## Socket 44X1
designator CN?
pins: 1, 2, 3, 4, 5, 6, 7, 8, 9, 10, 11, 12, 13, 14, 15, 16, 17, 18, 19, 20, 21, 22, 23, 24, 25, 26, 27, 28, 29, 30, 31, 32, 33, 34, 35, 36, 37, 38, 39, 40, 41, 42, 43, 44

## Socket 44X2 Paired
designator CN?
pins: 1 1-1, 2 2-2, 3 3-3, 4 4-4, 5 5-5, 6 6-6, 7 7-7, 8 8-8, 9 9-9, 10 10-10, 11 11-11, 12 12-12, 13 13-13, 14 14-14, 15 15-15, 16 16-16, 17 17-17, 18 18-18, 19 19-19, 20 20-20, 21 21-21, 22 22-22, 23 23-23, 24 24-24, 25 25-25, 26 26-26, 27 27-27, 28 28-28, 29 29-29, 30 30-30, 31 31-31, 32 32-32, 33 33-33, 34 34-34, 35 35-35, 36 36-36, 37 37-37, 38 38-38, 39 39-39, 40 40-40, 41 41-41, 42 42-42, 43 43-43, 44 44-44

## Socket 45X1
designator CN?
pins: 1, 2, 3, 4, 5, 6, 7, 8, 9, 10, 11, 12, 13, 14, 15, 16, 17, 18, 19, 20, 21, 22, 23, 24, 25, 26, 27, 28, 29, 30, 31, 32, 33, 34, 35, 36, 37, 38, 39, 40, 41, 42, 43, 44, 45

## Socket 45X2 Paired
designator CN?
pins: 1 1-1, 2 2-2, 3 3-3, 4 4-4, 5 5-5, 6 6-6, 7 7-7, 8 8-8, 9 9-9, 10 10-10, 11 11-11, 12 12-12, 13 13-13, 14 14-14, 15 15-15, 16 16-16, 17 17-17, 18 18-18, 19 19-19, 20 20-20, 21 21-21, 22 22-22, 23 23-23, 24 24-24, 25 25-25, 26 26-26, 27 27-27, 28 28-28, 29 29-29, 30 30-30, 31 31-31, 32 32-32, 33 33-33, 34 34-34, 35 35-35, 36 36-36, 37 37-37, 38 38-38, 39 39-39, 40 40-40, 41 41-41, 42 42-42, 43 43-43, 44 44-44, 45 45-45

## Socket QSH-030-01-F-D-A_DSI_LCD
designator CN?
pins: 1, 2, 3, 4, 5, 6, 7, 8, 9, 10, 11, 12, 13, 14, 15, 16, 17, 18, 19, 20, 21, 22, 23, 24, 25, 26, 27, 28, 29, 30, 31, 32, 33, 34, 35, 36, 37, 38, 39, 40, 41, 42, 43, 44, 45, 46, 47, 48, 49, 50, 51, 52, 53, 54, 55, 56, 57, 58, 59, 60, 61, 62, 63, 64

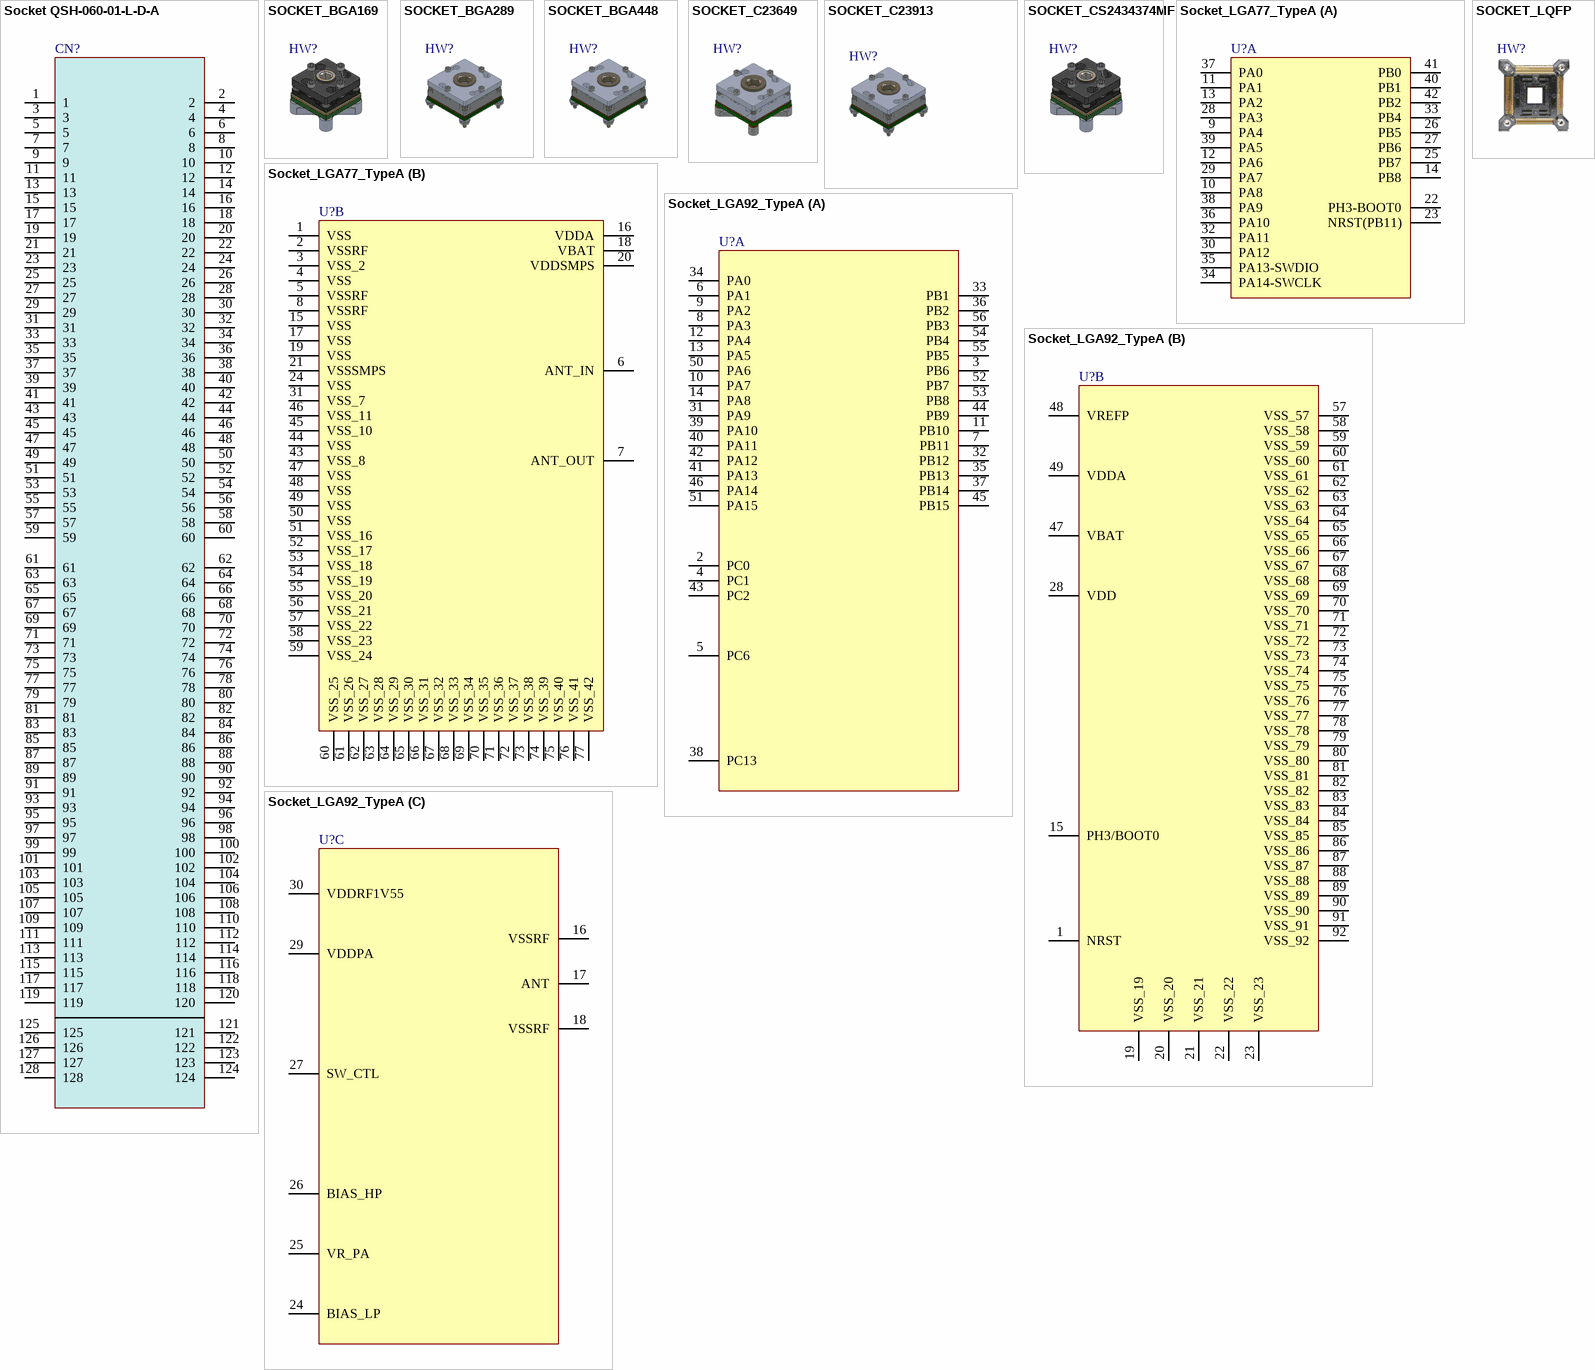
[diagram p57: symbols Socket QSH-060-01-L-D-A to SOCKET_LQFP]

## Socket QSH-060-01-L-D-A
designator CN?
pins: 1, 2, 3, 4, 5, 6, 7, 8, 9, 10, 11, 12, 13, 14, 15, 16, 17, 18, 19, 20, 21, 22, 23, 24, 25, 26, 27, 28, 29, 30, 31, 32, 33, 34, 35, 36, 37, 38, 39, 40, 41, 42, 43, 44, 45, 46, 47, 48, 49, 50, 51, 52, 53, 54, 55, 56, 57, 58, 59, 60, 61, 62, 63, 64, 65, 66, 67, 68, 69, 70, 71, 72, 73, 74, 75, 76, 77, 78, 79, 80, 81, 82, 83, 84, 85, 86, 87, 88, 89, 90, 91, 92, 93, 94, 95, 96, 97, 98, 99, 100, 101, 102, 103, 104, 105, 106, 107, 108, 109, 110, 111, 112, 113, 114, 115, 116, 117, 118, 119, 120, 121, 122, 123, 124, 125, 126, 127, 128

## SOCKET_BGA169
designator HW?  (mechanical)

## SOCKET_BGA289
designator HW?  (mechanical)

## SOCKET_BGA448
designator HW?  (mechanical)

## SOCKET_C23649
designator HW?

## SOCKET_C23913
designator HW?

## SOCKET_CS2434374MF
designator HW?

## Socket_LGA77_TypeA
designator U?
part A pins: 9 PA4, 10 PA8, 11 PA1, 12 PA6, 13 PA2, 14 PB8, 22 PH3-BOOT0, 23 NRST(PB11), 25 PB7, 26 PB5, 27 PB6, 28 PA3, 29 PA7, 30 PA12, 32 PA11, 33 PB4, 34 PA14-SWCLK, 35 PA13-SWDIO, 36 PA10, 37 PA0, 38 PA9, 39 PA5, 40 PB1, 41 PB0, 42 PB2
part B pins: 1 VSS, 2 VSSRF, 3 VSS_2, 4 VSS, 5 VSSRF, 6 ANT_IN, 7 ANT_OUT, 8 VSSRF, 15 VSS, 16 VDDA, 17 VSS, 18 VBAT, 19 VSS, 20 VDDSMPS, 21 VSSSMPS, 24 VSS, 31 VSS_7, 43 VSS_8, 44 VSS, 45 VSS_10, 46 VSS_11, 47 VSS, 48 VSS, 49 VSS, 50 VSS, 51 VSS_16, 52 VSS_17, 53 VSS_18, 54 VSS_19, 55 VSS_20, 56 VSS_21, 57 VSS_22, 58 VSS_23, 59 VSS_24, 60 VSS_25, 61 VSS_26, 62 VSS_27, 63 VSS_28, 64 VSS_29, 65 VSS_30, 66 VSS_31, 67 VSS_32, 68 VSS_33, 69 VSS_34, 70 VSS_35, 71 VSS_36, 72 VSS_37, 73 VSS_38, 74 VSS_39, 75 VSS_40, 76 VSS_41, 77 VSS_42

## Socket_LGA92_TypeA
designator U?
part A pins: 2 PC0, 3 PB6, 4 PC1, 5 PC6, 6 PA1, 7 PB11, 8 PA3, 9 PA2, 10 PA7, 11 PB10, 12 PA4, 13 PA5, 14 PA8, 31 PA9, 32 PB12, 33 PB1, 34 PA0, 35 PB13, 36 PB2, 37 PB14, 38 PC13, 39 PA10, 40 PA11, 41 PA13, 42 PA12, 43 PC2, 44 PB9, 45 PB15, 46 PA14, 50 PA6, 51 PA15, 52 PB7, 53 PB8, 54 PB4, 55 PB5, 56 PB3
part B pins: 1 NRST, 15 PH3/BOOT0, 19 VSS_19, 20 VSS_20, 21 VSS_21, 22 VSS_22, 23 VSS_23, 28 VDD, 47 VBAT, 48 VREFP, 49 VDDA, 57 VSS_57, 58 VSS_58, 59 VSS_59, 60 VSS_60, 61 VSS_61, 62 VSS_62, 63 VSS_63, 64 VSS_64, 65 VSS_65, 66 VSS_66, 67 VSS_67, 68 VSS_68, 69 VSS_69, 70 VSS_70, 71 VSS_71, 72 VSS_72, 73 VSS_73, 74 VSS_74, 75 VSS_75, 76 VSS_76, 77 VSS_77, 78 VSS_78, 79 VSS_79, 80 VSS_80, 81 VSS_81, 82 VSS_82, 83 VSS_83, 84 VSS_84, 85 VSS_85, 86 VSS_86, 87 VSS_87, 88 VSS_88, 89 VSS_89, 90 VSS_90, 91 VSS_91, 92 VSS_92
part C pins: 16 VSSRF, 17 ANT, 18 VSSRF, 24 BIAS_LP, 25 VR_PA, 26 BIAS_HP, 27 SW_CTL, 29 VDDPA, 30 VDDRF1V55

## SOCKET_LQFP
designator HW?  (mechanical)

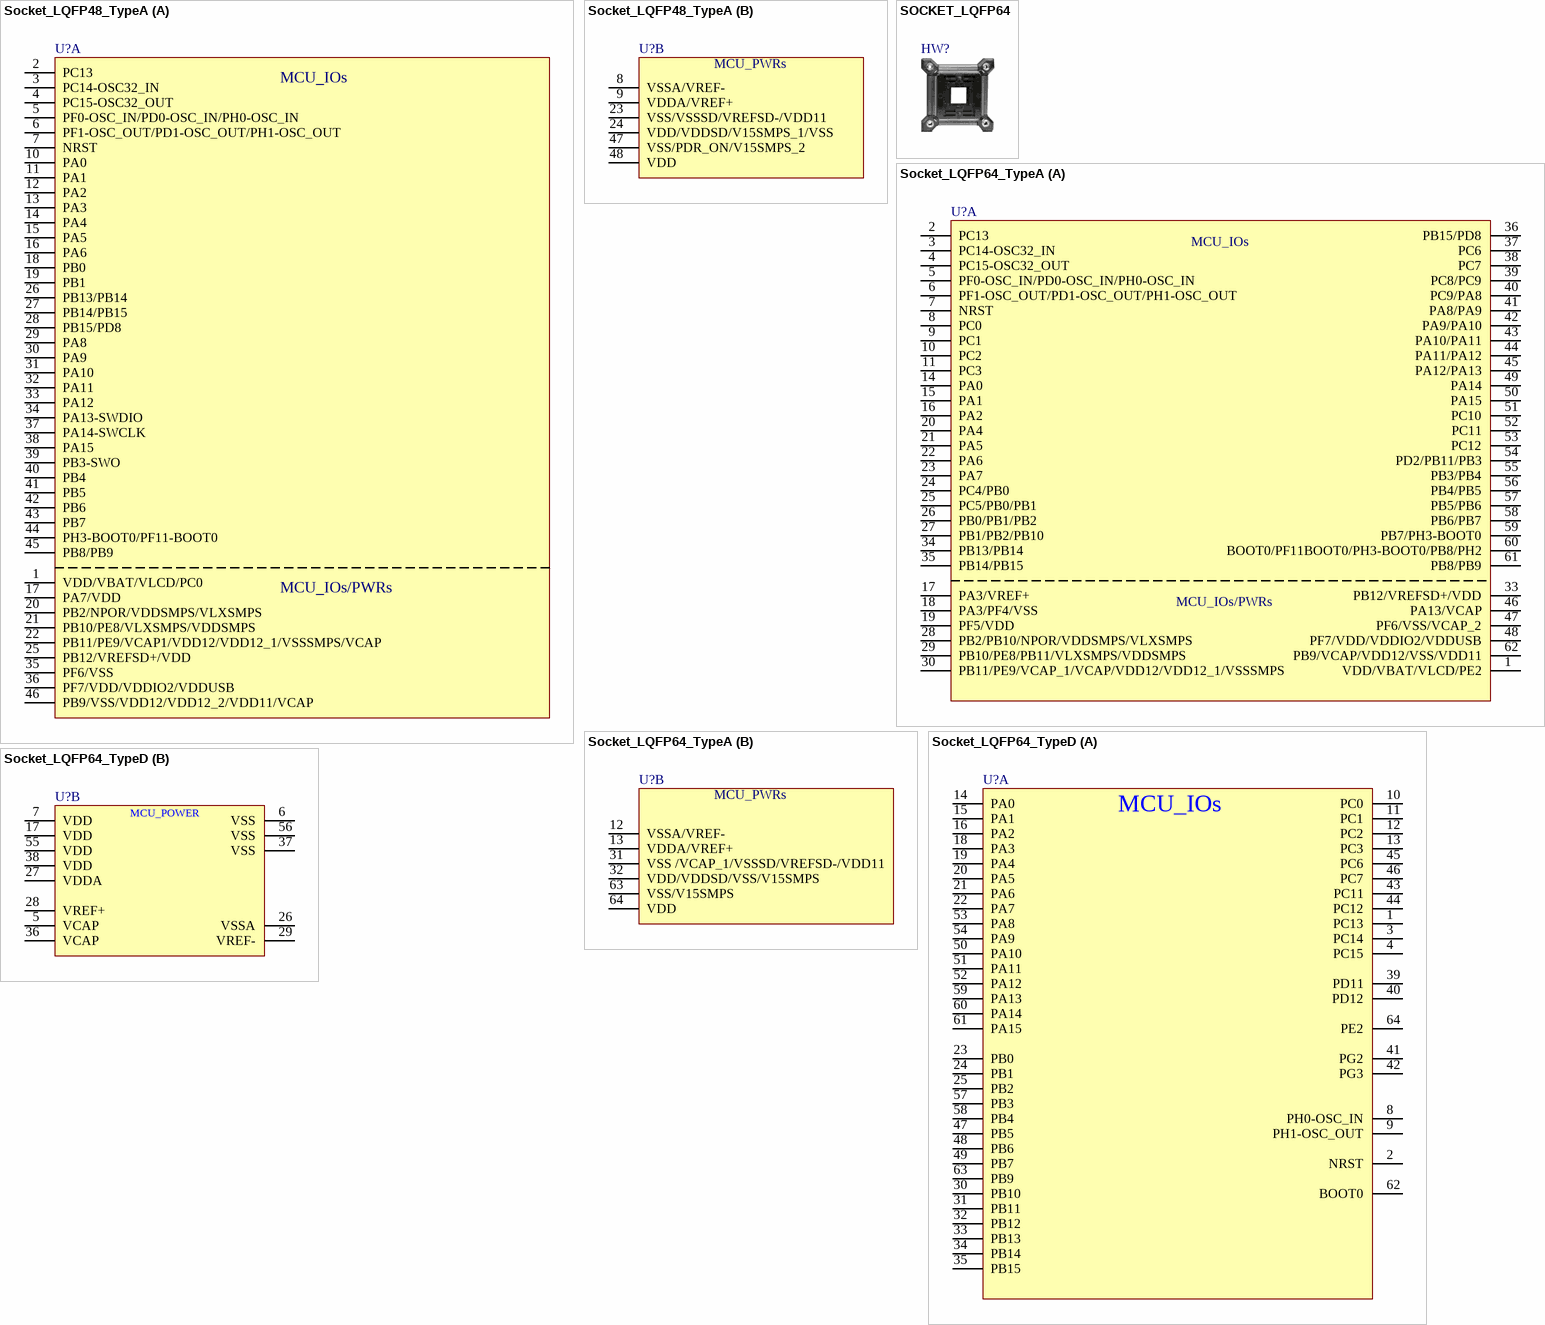
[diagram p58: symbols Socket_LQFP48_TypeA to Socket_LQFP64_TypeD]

## Socket_LQFP48_TypeA
designator U?
part A pins: 1 VDD/VBAT/VLCD/PC0, 2 PC13, 3 PC14-OSC32_IN, 4 PC15-OSC32_OUT, 5 PF0-OSC_IN/PD0-OSC_IN/PH0-OSC_IN, 6 PF1-OSC_OUT/PD1-OSC_OUT/PH1-OSC_OUT, 7 NRST, 10 PA0, 11 PA1, 12 PA2, 13 PA3, 14 PA4, 15 PA5, 16 PA6, 17 PA7/VDD, 18 PB0, 19 PB1, 20 PB2/NPOR/VDDSMPS/VLXSMPS, 21 PB10/PE8/VLXSMPS/VDDSMPS, 22 PB11/PE9/VCAP1/VDD12/VDD12_1/VSSSMPS/VCAP, 25 PB12/VREFSD+/VDD, 26 PB13/PB14, 27 PB14/PB15, 28 PB15/PD8, 29 PA8, 30 PA9, 31 PA10, 32 PA11, 33 PA12, 34 PA13-SWDIO, 35 PF6/VSS, 36 PF7/VDD/VDDIO2/VDDUSB, 37 PA14-SWCLK, 38 PA15, 39 PB3-SWO, 40 PB4, 41 PB5, 42 PB6, 43 PB7, 44 PH3-BOOT0/PF11-BOOT0, 45 PB8/PB9, 46 PB9/VSS/VDD12/VDD12_2/VDD11/VCAP
part B pins: 8 VSSA/VREF-, 9 VDDA/VREF+, 23 VSS/VSSSD/VREFSD-/VDD11, 24 VDD/VDDSD/V15SMPS_1/VSS, 47 VSS/PDR_ON/V15SMPS_2, 48 VDD

## SOCKET_LQFP64
designator HW?  (mechanical)

## Socket_LQFP64_TypeA
designator U?
part A pins: 1 VDD/VBAT/VLCD/PE2, 2 PC13, 3 PC14-OSC32_IN, 4 PC15-OSC32_OUT, 5 PF0-OSC_IN/PD0-OSC_IN/PH0-OSC_IN, 6 PF1-OSC_OUT/PD1-OSC_OUT/PH1-OSC_OUT, 7 NRST, 8 PC0, 9 PC1, 10 PC2, 11 PC3, 14 PA0, 15 PA1, 16 PA2, 17 PA3/VREF+, 18 PA3/PF4/VSS, 19 PF5/VDD, 20 PA4, 21 PA5, 22 PA6, 23 PA7, 24 PC4/PB0, 25 PC5/PB0/PB1, 26 PB0/PB1/PB2, 27 PB1/PB2/PB10, 28 PB2/PB10/NPOR/VDDSMPS/VLXSMPS, 29 PB10/PE8/PB11/VLXSMPS/VDDSMPS, 30 PB11/PE9/VCAP_1/VCAP/VDD12/VDD12_1/VSSSMPS, 33 PB12/VREFSD+/VDD, 34 PB13/PB14, 35 PB14/PB15, 36 PB15/PD8, 37 PC6, 38 PC7, 39 PC8/PC9, 40 PC9/PA8, 41 PA8/PA9, 42 PA9/PA10, 43 PA10/PA11, 44 PA11/PA12, 45 PA12/PA13, 46 PA13/VCAP, 47 PF6/VSS/VCAP_2, 48 PF7/VDD/VDDIO2/VDDUSB, 49 PA14, 50 PA15, 51 PC10, 52 PC11, 53 PC12, 54 PD2/PB11/PB3, 55 PB3/PB4, 56 PB4/PB5, 57 PB5/PB6, 58 PB6/PB7, 59 PB7/PH3-BOOT0, 60 BOOT0/PF11BOOT0/PH3-BOOT0/PB8/PH2, 61 PB8/PB9, 62 PB9/VCAP/VDD12/VSS/VDD11
part B pins: 12 VSSA/VREF-, 13 VDDA/VREF+, 31 VSS /VCAP_1/VSSSD/VREFSD-/VDD11, 32 VDD/VDDSD/VSS/V15SMPS, 63 VSS/V15SMPS, 64 VDD

## Socket_LQFP64_TypeD
designator U?
part A pins: 1 PC13, 2 NRST, 3 PC14, 4 PC15, 8 PH0-OSC_IN, 9 PH1-OSC_OUT, 10 PC0, 11 PC1, 12 PC2, 13 PC3, 14 PA0, 15 PA1, 16 PA2, 18 PA3, 19 PA4, 20 PA5, 21 PA6, 22 PA7, 23 PB0, 24 PB1, 25 PB2, 30 PB10, 31 PB11, 32 PB12, 33 PB13, 34 PB14, 35 PB15, 39 PD11, 40 PD12, 41 PG2, 42 PG3, 43 PC11, 44 PC12, 45 PC6, 46 PC7, 47 PB5, 48 PB6, 49 PB7, 50 PA10, 51 PA11, 52 PA12, 53 PA8, 54 PA9, 57 PB3, 58 PB4, 59 PA13, 60 PA14, 61 PA15, 62 BOOT0, 63 PB9, 64 PE2
part B pins: 5 VCAP, 6 VSS, 7 VDD, 17 VDD, 26 VSSA, 27 VDDA, 28 VREF+, 29 VREF-, 36 VCAP, 37 VSS, 38 VDD, 55 VDD, 56 VSS

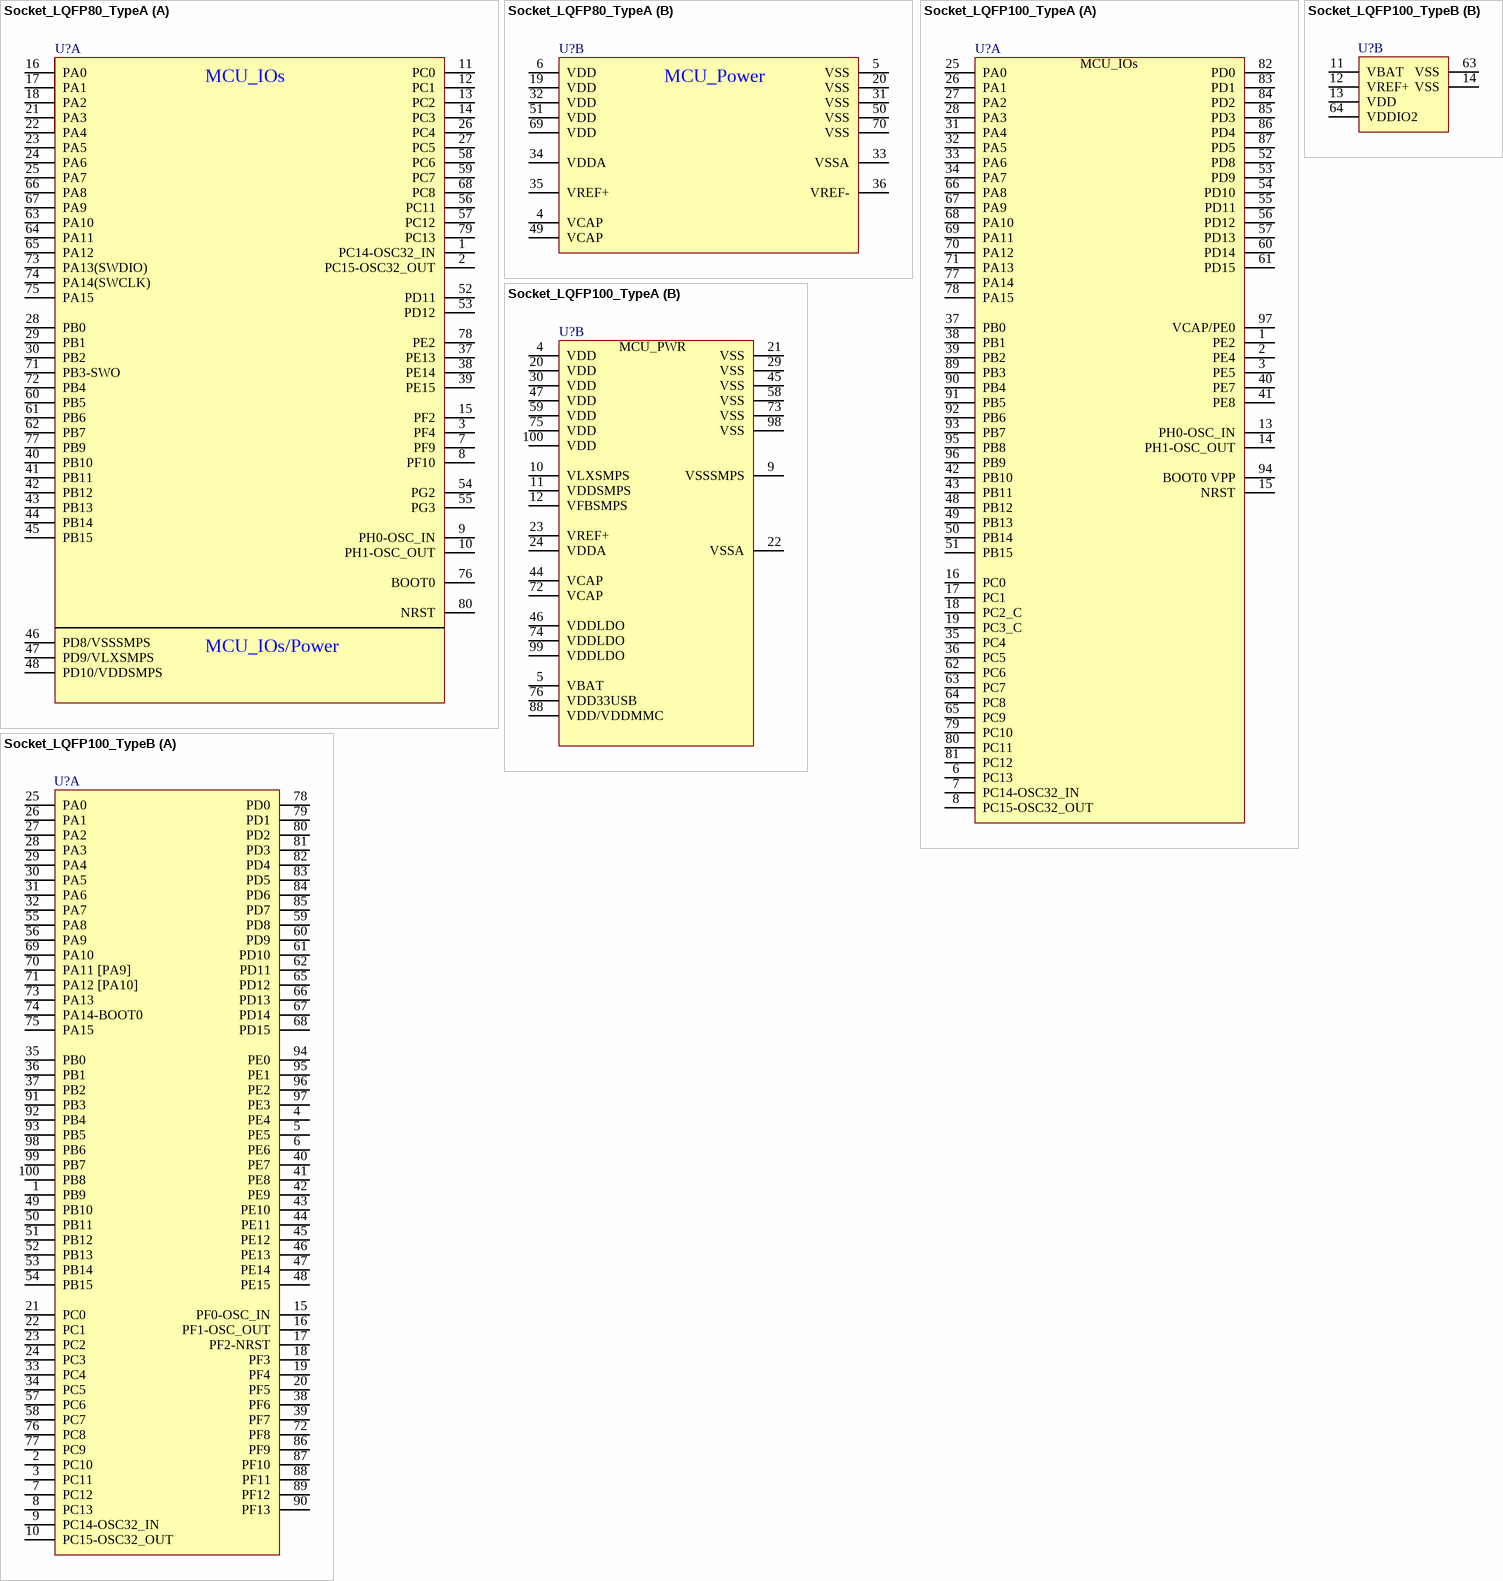
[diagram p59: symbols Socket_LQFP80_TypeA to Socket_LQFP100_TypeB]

## Socket_LQFP80_TypeA
designator U?
part A pins: 1 PC14-OSC32_IN, 2 PC15-OSC32_OUT, 3 PF4, 7 PF9, 8 PF10, 9 PH0-OSC_IN, 10 PH1-OSC_OUT, 11 PC0, 12 PC1, 13 PC2, 14 PC3, 15 PF2, 16 PA0, 17 PA1, 18 PA2, 21 PA3, 22 PA4, 23 PA5, 24 PA6, 25 PA7, 26 PC4, 27 PC5, 28 PB0, 29 PB1, 30 PB2, 37 PE13, 38 PE14, 39 PE15, 40 PB10, 41 PB11, 42 PB12, 43 PB13, 44 PB14, 45 PB15, 46 PD8/VSSSMPS, 47 PD9/VLXSMPS, 48 PD10/VDDSMPS, 52 PD11, 53 PD12, 54 PG2, 55 PG3, 56 PC11, 57 PC12, 58 PC6, 59 PC7, 60 PB5, 61 PB6, 62 PB7, 63 PA10, 64 PA11, 65 PA12, 66 PA8, 67 PA9, 68 PC8, 71 PB3-SWO, 72 PB4, 73 PA13(SWDIO), 74 PA14(SWCLK), 75 PA15, 76 BOOT0, 77 PB9, 78 PE2, 79 PC13, 80 NRST
part B pins: 4 VCAP, 5 VSS, 6 VDD, 19 VDD, 20 VSS, 31 VSS, 32 VDD, 33 VSSA, 34 VDDA, 35 VREF+, 36 VREF-, 49 VCAP, 50 VSS, 51 VDD, 69 VDD, 70 VSS

## Socket_LQFP100_TypeA
designator U?
part A pins: 1 PE2, 2 PE4, 3 PE5, 6 PC13, 7 PC14-OSC32_IN, 8 PC15-OSC32_OUT, 13 PH0-OSC_IN, 14 PH1-OSC_OUT, 15 NRST, 16 PC0, 17 PC1, 18 PC2_C, 19 PC3_C, 25 PA0, 26 PA1, 27 PA2, 28 PA3, 31 PA4, 32 PA5, 33 PA6, 34 PA7, 35 PC4, 36 PC5, 37 PB0, 38 PB1, 39 PB2, 40 PE7, 41 PE8, 42 PB10, 43 PB11, 48 PB12, 49 PB13, 50 PB14, 51 PB15, 52 PD8, 53 PD9, 54 PD10, 55 PD11, 56 PD12, 57 PD13, 60 PD14, 61 PD15, 62 PC6, 63 PC7, 64 PC8, 65 PC9, 66 PA8, 67 PA9, 68 PA10, 69 PA11, 70 PA12, 71 PA13, 77 PA14, 78 PA15, 79 PC10, 80 PC11, 81 PC12, 82 PD0, 83 PD1, 84 PD2, 85 PD3, 86 PD4, 87 PD5, 89 PB3, 90 PB4, 91 PB5, 92 PB6, 93 PB7, 94 BOOT0 VPP, 95 PB8, 96 PB9, 97 VCAP/PE0
part B pins: 4 VDD, 5 VBAT, 9 VSSSMPS, 10 VLXSMPS, 11 VDDSMPS, 12 VFBSMPS, 20 VDD, 21 VSS, 22 VSSA, 23 VREF+, 24 VDDA, 29 VSS, 30 VDD, 44 VCAP, 45 VSS, 46 VDDLDO, 47 VDD, 58 VSS, 59 VDD, 72 VCAP, 73 VSS, 74 VDDLDO, 75 VDD, 76 VDD33USB, 88 VDD/VDDMMC, 98 VSS, 99 VDDLDO, 100 VDD

## Socket_LQFP100_TypeB
designator U?
part A pins: 1 PB9, 2 PC10, 3 PC11, 4 PE4, 5 PE5, 6 PE6, 7 PC12, 8 PC13, 9 PC14-OSC32_IN, 10 PC15-OSC32_OUT, 15 PF0-OSC_IN, 16 PF1-OSC_OUT, 17 PF2-NRST, 18 PF3, 19 PF4, 20 PF5, 21 PC0, 22 PC1, 23 PC2, 24 PC3, 25 PA0, 26 PA1, 27 PA2, 28 PA3, 29 PA4, 30 PA5, 31 PA6, 32 PA7, 33 PC4, 34 PC5, 35 PB0, 36 PB1, 37 PB2, 38 PF6, 39 PF7, 40 PE7, 41 PE8, 42 PE9, 43 PE10, 44 PE11, 45 PE12, 46 PE13, 47 PE14, 48 PE15, 49 PB10, 50 PB11, 51 PB12, 52 PB13, 53 PB14, 54 PB15, 55 PA8, 56 PA9, 57 PC6, 58 PC7, 59 PD8, 60 PD9, 61 PD10, 62 PD11, 65 PD12, 66 PD13, 67 PD14, 68 PD15, 69 PA10, 70 PA11 [PA9], 71 PA12 [PA10], 72 PF8, 73 PA13, 74 PA14-BOOT0, 75 PA15, 76 PC8, 77 PC9, 78 PD0, 79 PD1, 80 PD2, 81 PD3, 82 PD4, 83 PD5, 84 PD6, 85 PD7, 86 PF9, 87 PF10, 88 PF11, 89 PF12, 90 PF13, 91 PB3, 92 PB4, 93 PB5, 94 PE0, 95 PE1, 96 PE2, 97 PE3, 98 PB6, 99 PB7, 100 PB8
part B pins: 11 VBAT, 12 VREF+, 13 VDD, 14 VSS, 63 VSS, 64 VDDIO2

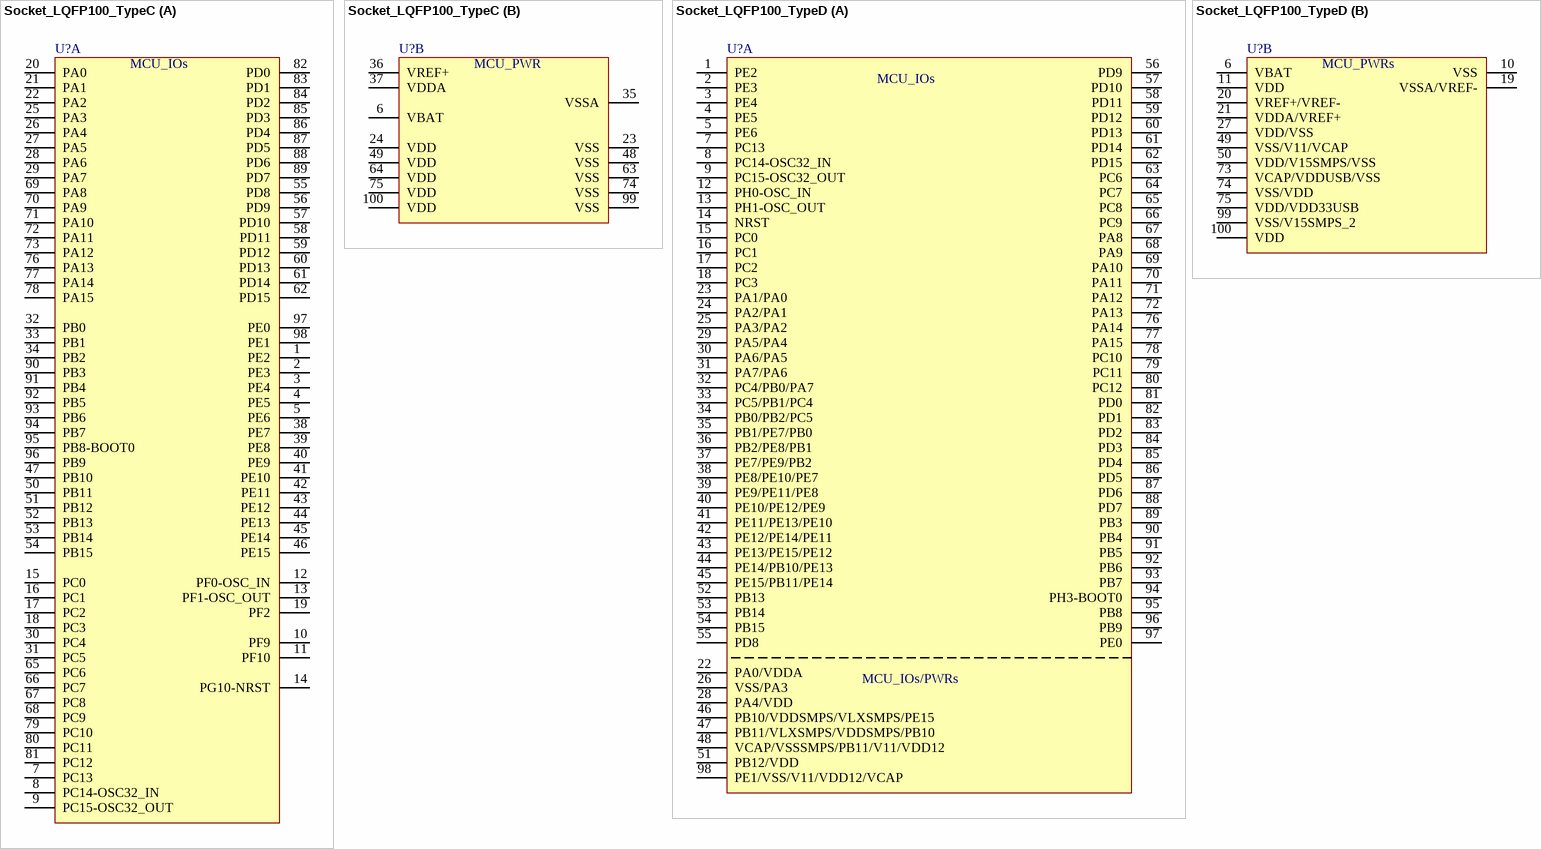
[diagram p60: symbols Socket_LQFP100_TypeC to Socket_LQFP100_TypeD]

## Socket_LQFP100_TypeC
designator U?
part A pins: 1 PE2, 2 PE3, 3 PE4, 4 PE5, 5 PE6, 7 PC13, 8 PC14-OSC32_IN, 9 PC15-OSC32_OUT, 10 PF9, 11 PF10, 12 PF0-OSC_IN, 13 PF1-OSC_OUT, 14 PG10-NRST, 15 PC0, 16 PC1, 17 PC2, 18 PC3, 19 PF2, 20 PA0, 21 PA1, 22 PA2, 25 PA3, 26 PA4, 27 PA5, 28 PA6, 29 PA7, 30 PC4, 31 PC5, 32 PB0, 33 PB1, 34 PB2, 38 PE7, 39 PE8, 40 PE9, 41 PE10, 42 PE11, 43 PE12, 44 PE13, 45 PE14, 46 PE15, 47 PB10, 50 PB11, 51 PB12, 52 PB13, 53 PB14, 54 PB15, 55 PD8, 56 PD9, 57 PD10, 58 PD11, 59 PD12, 60 PD13, 61 PD14, 62 PD15, 65 PC6, 66 PC7, 67 PC8, 68 PC9, 69 PA8, 70 PA9, 71 PA10, 72 PA11, 73 PA12, 76 PA13, 77 PA14, 78 PA15, 79 PC10, 80 PC11, 81 PC12, 82 PD0, 83 PD1, 84 PD2, 85 PD3, 86 PD4, 87 PD5, 88 PD6, 89 PD7, 90 PB3, 91 PB4, 92 PB5, 93 PB6, 94 PB7, 95 PB8-BOOT0, 96 PB9, 97 PE0, 98 PE1
part B pins: 6 VBAT, 23 VSS, 24 VDD, 35 VSSA, 36 VREF+, 37 VDDA, 48 VSS, 49 VDD, 63 VSS, 64 VDD, 74 VSS, 75 VDD, 99 VSS, 100 VDD

## Socket_LQFP100_TypeD
designator U?
part A pins: 1 PE2, 2 PE3, 3 PE4, 4 PE5, 5 PE6, 7 PC13, 8 PC14-OSC32_IN, 9 PC15-OSC32_OUT, 12 PH0-OSC_IN, 13 PH1-OSC_OUT, 14 NRST, 15 PC0, 16 PC1, 17 PC2, 18 PC3, 22 PA0/VDDA, 23 PA1/PA0, 24 PA2/PA1, 25 PA3/PA2, 26 VSS/PA3, 28 PA4/VDD, 29 PA5/PA4, 30 PA6/PA5, 31 PA7/PA6, 32 PC4/PB0/PA7, 33 PC5/PB1/PC4, 34 PB0/PB2/PC5, 35 PB1/PE7/PB0, 36 PB2/PE8/PB1, 37 PE7/PE9/PB2, 38 PE8/PE10/PE7, 39 PE9/PE11/PE8, 40 PE10/PE12/PE9, 41 PE11/PE13/PE10, 42 PE12/PE14/PE11, 43 PE13/PE15/PE12, 44 PE14/PB10/PE13, 45 PE15/PB11/PE14, 46 PB10/VDDSMPS/VLXSMPS/PE15, 47 PB11/VLXSMPS/VDDSMPS/PB10, 48 VCAP/VSSSMPS/PB11/V11/VDD12, 51 PB12/VDD, 52 PB13, 53 PB14, 54 PB15, 55 PD8, 56 PD9, 57 PD10, 58 PD11, 59 PD12, 60 PD13, 61 PD14, 62 PD15, 63 PC6, 64 PC7, 65 PC8, 66 PC9, 67 PA8, 68 PA9, 69 PA10, 70 PA11, 71 PA12, 72 PA13, 76 PA14, 77 PA15, 78 PC10, 79 PC11, 80 PC12, 81 PD0, 82 PD1, 83 PD2, 84 PD3, 85 PD4, 86 PD5, 87 PD6, 88 PD7, 89 PB3, 90 PB4, 91 PB5, 92 PB6, 93 PB7, 94 PH3-BOOT0, 95 PB8, 96 PB9, 97 PE0, 98 PE1/VSS/V11/VDD12/VCAP
part B pins: 6 VBAT, 10 VSS, 11 VDD, 19 VSSA/VREF-, 20 VREF+/VREF-, 21 VDDA/VREF+, 27 VDD/VSS, 49 VSS/V11/VCAP, 50 VDD/V15SMPS/VSS, 73 VCAP/VDDUSB/VSS, 74 VSS/VDD, 75 VDD/VDD33USB, 99 VSS/V15SMPS_2, 100 VDD

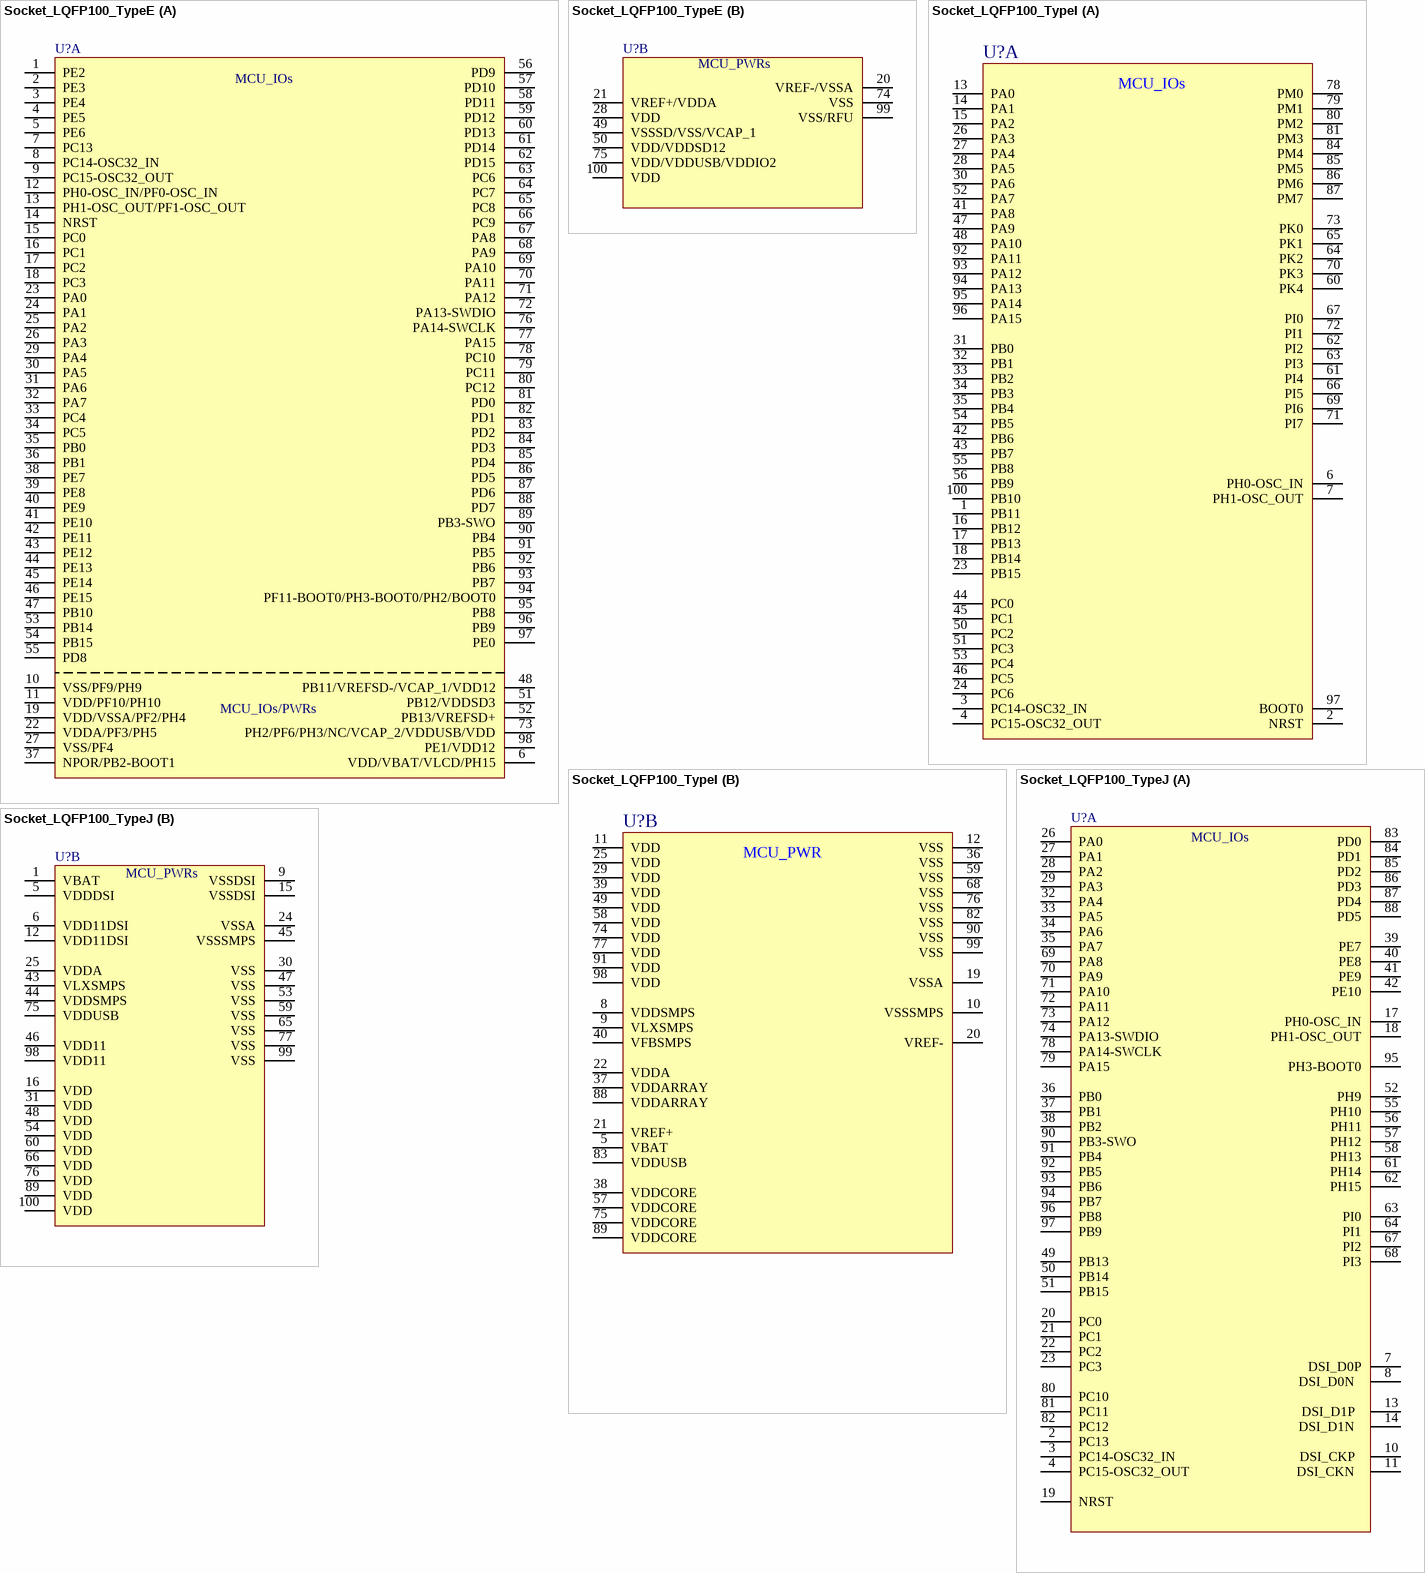
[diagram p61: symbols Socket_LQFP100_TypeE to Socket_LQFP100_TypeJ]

## Socket_LQFP100_TypeE
designator U?
part A pins: 1 PE2, 2 PE3, 3 PE4, 4 PE5, 5 PE6, 6 VDD/VBAT/VLCD/PH15, 7 PC13, 8 PC14-OSC32_IN, 9 PC15-OSC32_OUT, 10 VSS/PF9/PH9, 11 VDD/PF10/PH10, 12 PH0-OSC_IN/PF0-OSC_IN, 13 PH1-OSC_OUT/PF1-OSC_OUT, 14 NRST, 15 PC0, 16 PC1, 17 PC2, 18 PC3, 19 VDD/VSSA/PF2/PH4, 22 VDDA/PF3/PH5, 23 PA0, 24 PA1, 25 PA2, 26 PA3, 27 VSS/PF4, 29 PA4, 30 PA5, 31 PA6, 32 PA7, 33 PC4, 34 PC5, 35 PB0, 36 PB1, 37 NPOR/PB2-BOOT1, 38 PE7, 39 PE8, 40 PE9, 41 PE10, 42 PE11, 43 PE12, 44 PE13, 45 PE14, 46 PE15, 47 PB10, 48 PB11/VREFSD-/VCAP_1/VDD12, 51 PB12/VDDSD3, 52 PB13/VREFSD+, 53 PB14, 54 PB15, 55 PD8, 56 PD9, 57 PD10, 58 PD11, 59 PD12, 60 PD13, 61 PD14, 62 PD15, 63 PC6, 64 PC7, 65 PC8, 66 PC9, 67 PA8, 68 PA9, 69 PA10, 70 PA11, 71 PA12, 72 PA13-SWDIO, 73 PH2/PF6/PH3/NC/VCAP_2/VDDUSB/VDD, 76 PA14-SWCLK, 77 PA15, 78 PC10, 79 PC11, 80 PC12, 81 PD0, 82 PD1, 83 PD2, 84 PD3, 85 PD4, 86 PD5, 87 PD6, 88 PD7, 89 PB3-SWO, 90 PB4, 91 PB5, 92 PB6, 93 PB7, 94 PF11-BOOT0/PH3-BOOT0/PH2/BOOT0, 95 PB8, 96 PB9, 97 PE0, 98 PE1/VDD12
part B pins: 20 VREF-/VSSA, 21 VREF+/VDDA, 28 VDD, 49 VSSSD/VSS/VCAP_1, 50 VDD/VDDSD12, 74 VSS, 75 VDD/VDDUSB/VDDIO2, 99 VSS/RFU, 100 VDD

## Socket_LQFP100_TypeI
designator U?
part A pins: 1 PB11, 2 NRST, 3 PC14-OSC32_IN, 4 PC15-OSC32_OUT, 6 PH0-OSC_IN, 7 PH1-OSC_OUT, 13 PA0, 14 PA1, 15 PA2, 16 PB12, 17 PB13, 18 PB14, 23 PB15, 24 PC6, 26 PA3, 27 PA4, 28 PA5, 30 PA6, 31 PB0, 32 PB1, 33 PB2, 34 PB3, 35 PB4, 41 PA8, 42 PB6, 43 PB7, 44 PC0, 45 PC1, 46 PC5, 47 PA9, 48 PA10, 50 PC2, 51 PC3, 52 PA7, 53 PC4, 54 PB5, 55 PB8, 56 PB9, 60 PK4, 61 PI4, 62 PI2, 63 PI3, 64 PK2, 65 PK1, 66 PI5, 67 PI0, 69 PI6, 70 PK3, 71 PI7, 72 PI1, 73 PK0, 78 PM0, 79 PM1, 80 PM2, 81 PM3, 84 PM4, 85 PM5, 86 PM6, 87 PM7, 92 PA11, 93 PA12, 94 PA13, 95 PA14, 96 PA15, 97 BOOT0, 100 PB10
part B pins: 5 VBAT, 8 VDDSMPS, 9 VLXSMPS, 10 VSSSMPS, 11 VDD, 12 VSS, 19 VSSA, 20 VREF-, 21 VREF+, 22 VDDA, 25 VDD, 29 VDD, 36 VSS, 37 VDDARRAY, 38 VDDCORE, 39 VDD, 40 VFBSMPS, 49 VDD, 57 VDDCORE, 58 VDD, 59 VSS, 68 VSS, 74 VDD, 75 VDDCORE, 76 VSS, 77 VDD, 82 VSS, 83 VDDUSB, 88 VDDARRAY, 89 VDDCORE, 90 VSS, 91 VDD, 98 VDD, 99 VSS

## Socket_LQFP100_TypeJ
designator U?
part A pins: 2 PC13, 3 PC14-OSC32_IN, 4 PC15-OSC32_OUT, 7 DSI_D0P, 8 DSI_D0N  , 10 DSI_CKP  , 11 DSI_CKN  , 13 DSI_D1P  , 14 DSI_D1N  , 17 PH0-OSC_IN, 18 PH1-OSC_OUT, 19 NRST, 20 PC0, 21 PC1, 22 PC2, 23 PC3, 26 PA0, 27 PA1, 28 PA2, 29 PA3, 32 PA4, 33 PA5, 34 PA6, 35 PA7, 36 PB0, 37 PB1, 38 PB2, 39 PE7, 40 PE8, 41 PE9, 42 PE10, 49 PB13, 50 PB14, 51 PB15, 52 PH9, 55 PH10, 56 PH11, 57 PH12, 58 PH13, 61 PH14, 62 PH15, 63 PI0, 64 PI1, 67 PI2, 68 PI3, 69 PA8, 70 PA9, 71 PA10, 72 PA11, 73 PA12, 74 PA13-SWDIO, 78 PA14-SWCLK, 79 PA15, 80 PC10, 81 PC11, 82 PC12, 83 PD0, 84 PD1, 85 PD2, 86 PD3, 87 PD4, 88 PD5, 90 PB3-SWO, 91 PB4, 92 PB5, 93 PB6, 94 PB7, 95 PH3-BOOT0, 96 PB8, 97 PB9
part B pins: 1 VBAT, 5 VDDDSI, 6 VDD11DSI, 9 VSSDSI, 12 VDD11DSI, 15 VSSDSI, 16 VDD, 24 VSSA, 25 VDDA, 30 VSS, 31 VDD, 43 VLXSMPS, 44 VDDSMPS, 45 VSSSMPS, 46 VDD11, 47 VSS, 48 VDD, 53 VSS, 54 VDD, 59 VSS, 60 VDD, 65 VSS, 66 VDD, 75 VDDUSB, 76 VDD, 77 VSS, 89 VDD, 98 VDD11, 99 VSS, 100 VDD

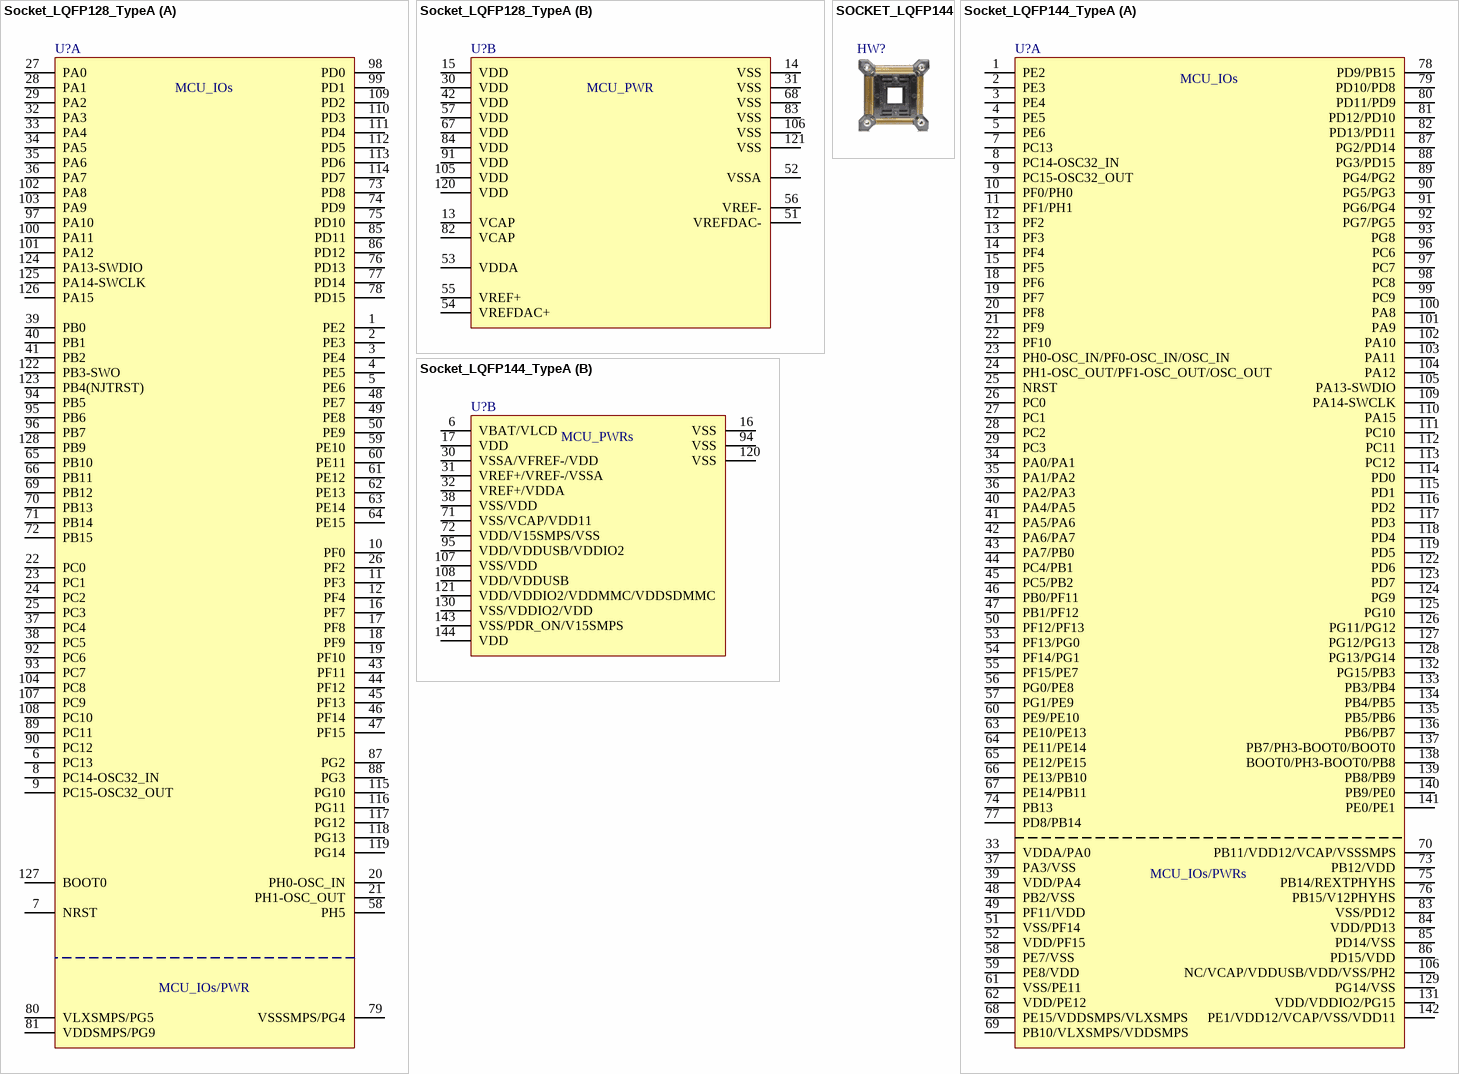
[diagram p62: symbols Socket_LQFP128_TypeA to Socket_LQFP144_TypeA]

## Socket_LQFP128_TypeA
designator U?
part A pins: 1 PE2, 2 PE3, 3 PE4, 4 PE5, 5 PE6, 6 PC13, 7 NRST, 8 PC14-OSC32_IN, 9 PC15-OSC32_OUT, 10 PF0, 11 PF3, 12 PF4, 16 PF7, 17 PF8, 18 PF9, 19 PF10, 20 PH0-OSC_IN, 21 PH1-OSC_OUT, 22 PC0, 23 PC1, 24 PC2, 25 PC3, 26 PF2, 27 PA0, 28 PA1, 29 PA2, 32 PA3, 33 PA4, 34 PA5, 35 PA6, 36 PA7, 37 PC4, 38 PC5, 39 PB0, 40 PB1, 41 PB2, 43 PF11, 44 PF12, 45 PF13, 46 PF14, 47 PF15, 48 PE7, 49 PE8, 50 PE9, 58 PH5, 59 PE10, 60 PE11, 61 PE12, 62 PE13, 63 PE14, 64 PE15, 65 PB10, 66 PB11, 69 PB12, 70 PB13, 71 PB14, 72 PB15, 73 PD8, 74 PD9, 75 PD10, 76 PD13, 77 PD14, 78 PD15, 79 VSSSMPS/PG4, 80 VLXSMPS/PG5, 81 VDDSMPS/PG9, 85 PD11, 86 PD12, 87 PG2, 88 PG3, 89 PC11, 90 PC12, 92 PC6, 93 PC7, 94 PB5, 95 PB6, 96 PB7, 97 PA10, 98 PD0, 99 PD1, 100 PA11, 101 PA12, 102 PA8, 103 PA9, 104 PC8, 107 PC9, 108 PC10, 109 PD2, 110 PD3, 111 PD4, 112 PD5, 113 PD6, 114 PD7, 115 PG10, 116 PG11, 117 PG12, 118 PG13, 119 PG14, 122 PB3-SWO, 123 PB4(NJTRST), 124 PA13-SWDIO, 125 PA14-SWCLK, 126 PA15, 127 BOOT0, 128 PB9
part B pins: 13 VCAP, 14 VSS, 15 VDD, 30 VDD, 31 VSS, 42 VDD, 51 VREFDAC-, 52 VSSA, 53 VDDA, 54 VREFDAC+, 55 VREF+, 56 VREF-, 57 VDD, 67 VDD, 68 VSS, 82 VCAP, 83 VSS, 84 VDD, 91 VDD, 105 VDD, 106 VSS, 120 VDD, 121 VSS

## SOCKET_LQFP144
designator HW?  (mechanical)

## Socket_LQFP144_TypeA
designator U?
part A pins: 1 PE2, 2 PE3, 3 PE4, 4 PE5, 5 PE6, 7 PC13, 8 PC14-OSC32_IN, 9 PC15-OSC32_OUT, 10 PF0/PH0, 11 PF1/PH1, 12 PF2, 13 PF3, 14 PF4, 15 PF5, 18 PF6, 19 PF7, 20 PF8, 21 PF9, 22 PF10, 23 PH0-OSC_IN/PF0-OSC_IN/OSC_IN, 24 PH1-OSC_OUT/PF1-OSC_OUT/OSC_OUT, 25 NRST, 26 PC0, 27 PC1, 28 PC2, 29 PC3, 33 VDDA/PA0, 34 PA0/PA1, 35 PA1/PA2, 36 PA2/PA3, 37 PA3/VSS, 39 VDD/PA4, 40 PA4/PA5, 41 PA5/PA6, 42 PA6/PA7, 43 PA7/PB0, 44 PC4/PB1, 45 PC5/PB2, 46 PB0/PF11, 47 PB1/PF12, 48 PB2/VSS, 49 PF11/VDD, 50 PF12/PF13, 51 VSS/PF14, 52 VDD/PF15, 53 PF13/PG0, 54 PF14/PG1, 55 PF15/PE7, 56 PG0/PE8, 57 PG1/PE9, 58 PE7/VSS, 59 PE8/VDD, 60 PE9/PE10, 61 VSS/PE11, 62 VDD/PE12, 63 PE10/PE13, 64 PE11/PE14, 65 PE12/PE15, 66 PE13/PB10, 67 PE14/PB11, 68 PE15/VDDSMPS/VLXSMPS, 69 PB10/VLXSMPS/VDDSMPS, 70 PB11/VDD12/VCAP/VSSSMPS, 73 PB12/VDD, 74 PB13, 75 PB14/REXTPHYHS, 76 PB15/V12PHYHS, 77 PD8/PB14, 78 PD9/PB15, 79 PD10/PD8, 80 PD11/PD9, 81 PD12/PD10, 82 PD13/PD11, 83 VSS/PD12, 84 VDD/PD13, 85 PD14/VSS, 86 PD15/VDD, 87 PG2/PD14, 88 PG3/PD15, 89 PG4/PG2, 90 PG5/PG3, 91 PG6/PG4, 92 PG7/PG5, 93 PG8, 96 PC6, 97 PC7, 98 PC8, 99 PC9, 100 PA8, 101 PA9, 102 PA10, 103 PA11, 104 PA12, 105 PA13-SWDIO, 106 NC/VCAP/VDDUSB/VDD/VSS/PH2, 109 PA14-SWCLK, 110 PA15, 111 PC10, 112 PC11, 113 PC12, 114 PD0, 115 PD1, 116 PD2, 117 PD3, 118 PD4, 119 PD5, 122 PD6, 123 PD7, 124 PG9, 125 PG10, 126 PG11/PG12, 127 PG12/PG13, 128 PG13/PG14, 129 PG14/VSS, 131 VDD/VDDIO2/PG15, 132 PG15/PB3, 133 PB3/PB4, 134 PB4/PB5, 135 PB5/PB6, 136 PB6/PB7, 137 PB7/PH3-BOOT0/BOOT0, 138 BOOT0/PH3-BOOT0/PB8, 139 PB8/PB9, 140 PB9/PE0, 141 PE0/PE1, 142 PE1/VDD12/VCAP/VSS/VDD11
part B pins: 6 VBAT/VLCD, 16 VSS, 17 VDD, 30 VSSA/VFREF-/VDD, 31 VREF+/VREF-/VSSA, 32 VREF+/VDDA, 38 VSS/VDD, 71 VSS/VCAP/VDD11, 72 VDD/V15SMPS/VSS, 94 VSS, 95 VDD/VDDUSB/VDDIO2, 107 VSS/VDD, 108 VDD/VDDUSB, 120 VSS, 121 VDD/VDDIO2/VDDMMC/VDDSDMMC, 130 VSS/VDDIO2/VDD, 143 VSS/PDR_ON/V15SMPS, 144 VDD

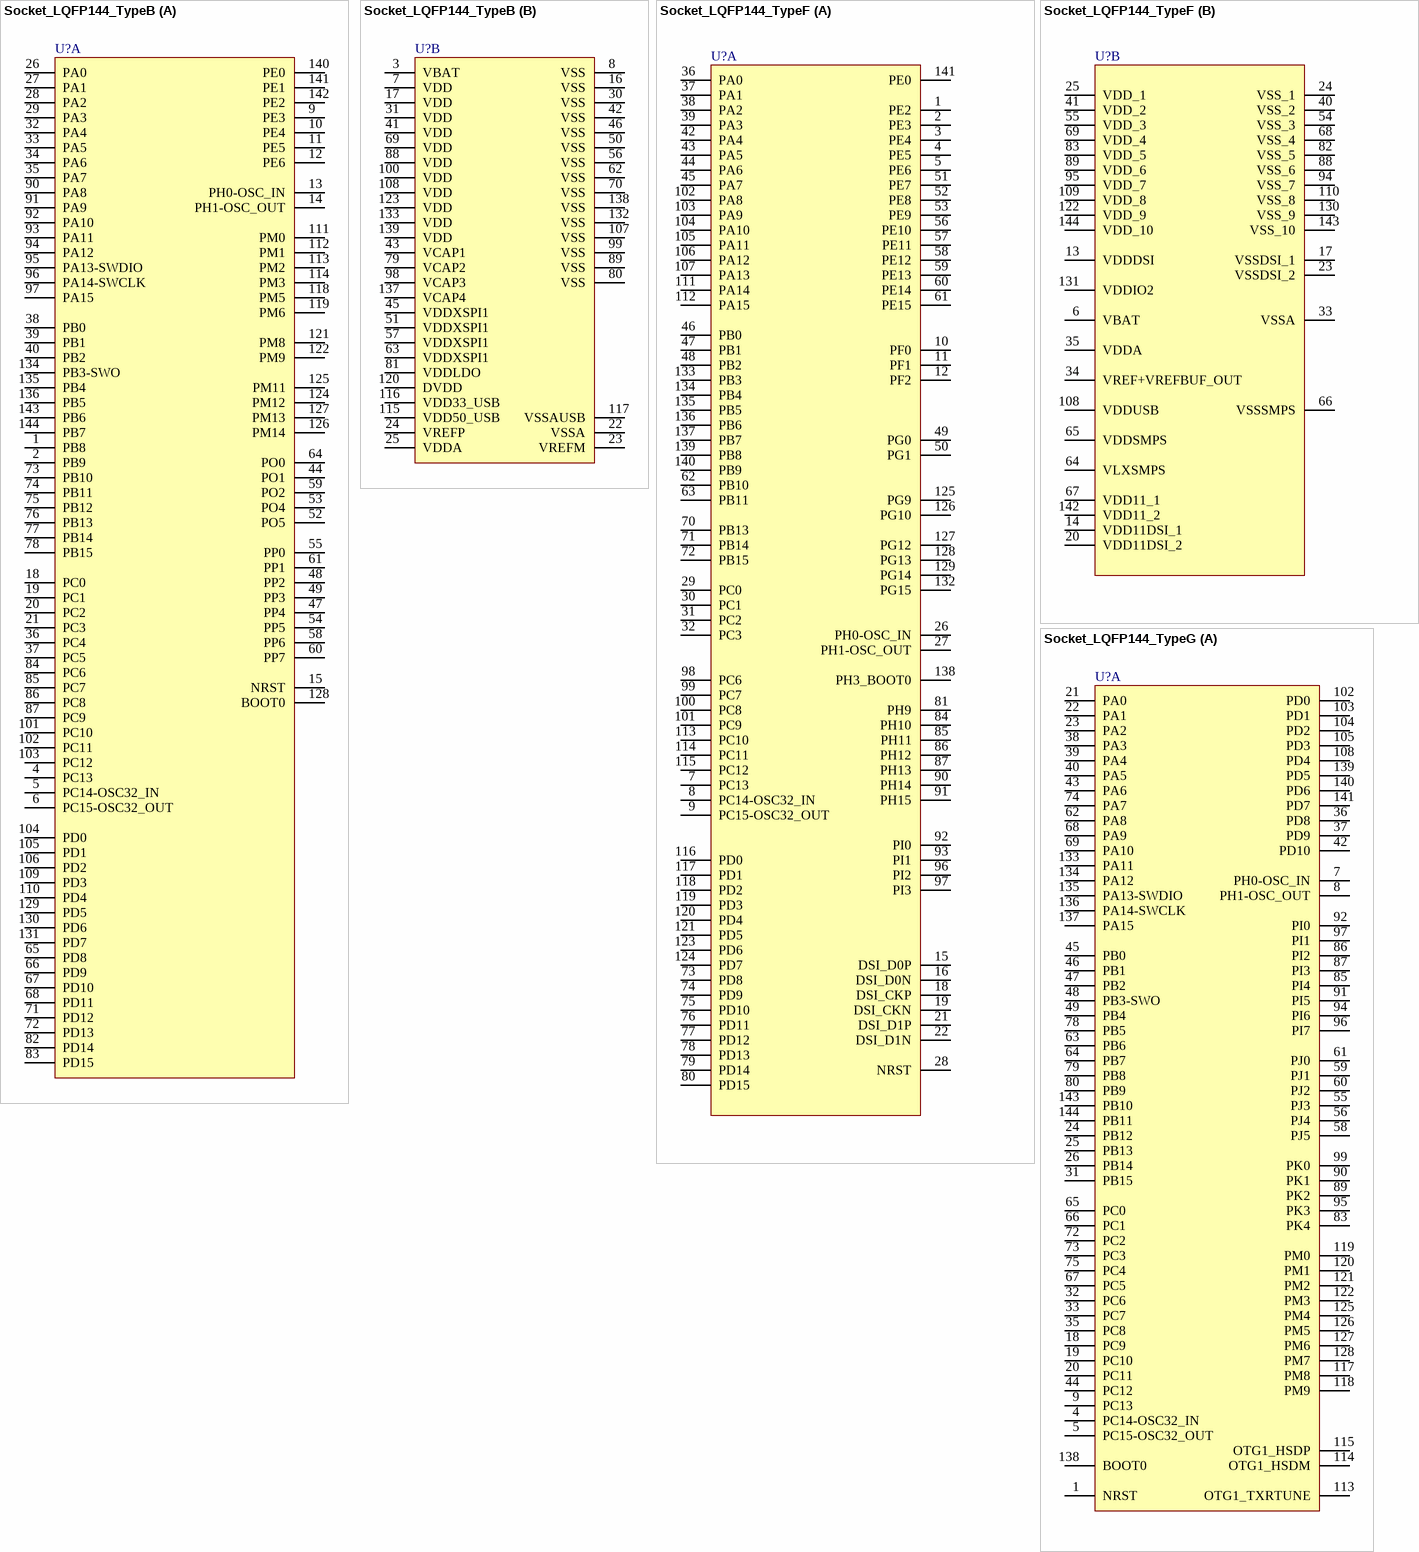
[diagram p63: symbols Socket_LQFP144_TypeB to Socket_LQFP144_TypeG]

## Socket_LQFP144_TypeB
designator U?
part A pins: 1 PB8, 2 PB9, 4 PC13, 5 PC14-OSC32_IN, 6 PC15-OSC32_OUT, 9 PE3, 10 PE4, 11 PE5, 12 PE6, 13 PH0-OSC_IN, 14 PH1-OSC_OUT, 15 NRST, 18 PC0, 19 PC1, 20 PC2, 21 PC3, 26 PA0, 27 PA1, 28 PA2, 29 PA3, 32 PA4, 33 PA5, 34 PA6, 35 PA7, 36 PC4, 37 PC5, 38 PB0, 39 PB1, 40 PB2, 44 PO1, 47 PP4, 48 PP2, 49 PP3, 52 PO5, 53 PO4, 54 PP5, 55 PP0, 58 PP6, 59 PO2, 60 PP7, 61 PP1, 64 PO0, 65 PD8, 66 PD9, 67 PD10, 68 PD11, 71 PD12, 72 PD13, 73 PB10, 74 PB11, 75 PB12, 76 PB13, 77 PB14, 78 PB15, 82 PD14, 83 PD15, 84 PC6, 85 PC7, 86 PC8, 87 PC9, 90 PA8, 91 PA9, 92 PA10, 93 PA11, 94 PA12, 95 PA13-SWDIO, 96 PA14-SWCLK, 97 PA15, 101 PC10, 102 PC11, 103 PC12, 104 PD0, 105 PD1, 106 PD2, 109 PD3, 110 PD4, 111 PM0, 112 PM1, 113 PM2, 114 PM3, 118 PM5, 119 PM6, 121 PM8, 122 PM9, 124 PM12, 125 PM11, 126 PM14, 127 PM13, 128 BOOT0, 129 PD5, 130 PD6, 131 PD7, 134 PB3-SWO, 135 PB4, 136 PB5, 140 PE0, 141 PE1, 142 PE2, 143 PB6, 144 PB7
part B pins: 3 VBAT, 7 VDD, 8 VSS, 16 VSS, 17 VDD, 22 VSSA, 23 VREFM, 24 VREFP, 25 VDDA, 30 VSS, 31 VDD, 41 VDD, 42 VSS, 43 VCAP1, 45 VDDXSPI1, 46 VSS, 50 VSS, 51 VDDXSPI1, 56 VSS, 57 VDDXSPI1, 62 VSS, 63 VDDXSPI1, 69 VDD, 70 VSS, 79 VCAP2, 80 VSS, 81 VDDLDO, 88 VDD, 89 VSS, 98 VCAP3, 99 VSS, 100 VDD, 107 VSS, 108 VDD, 115 VDD50_USB, 116 VDD33_USB, 117 VSSAUSB, 120 DVDD, 123 VDD, 132 VSS, 133 VDD, 137 VCAP4, 138 VSS, 139 VDD

## Socket_LQFP144_TypeF
designator U?
part A pins: 1 PE2, 2 PE3, 3 PE4, 4 PE5, 5 PE6, 7 PC13, 8 PC14-OSC32_IN, 9 PC15-OSC32_OUT, 10 PF0, 11 PF1, 12 PF2, 15 DSI_D0P, 16 DSI_D0N, 18 DSI_CKP, 19 DSI_CKN, 21 DSI_D1P, 22 DSI_D1N, 26 PH0-OSC_IN, 27 PH1-OSC_OUT, 28 NRST, 29 PC0, 30 PC1, 31 PC2, 32 PC3, 36 PA0, 37 PA1, 38 PA2, 39 PA3, 42 PA4, 43 PA5, 44 PA6, 45 PA7, 46 PB0, 47 PB1, 48 PB2, 49 PG0, 50 PG1, 51 PE7, 52 PE8, 53 PE9, 56 PE10, 57 PE11, 58 PE12, 59 PE13, 60 PE14, 61 PE15, 62 PB10, 63 PB11, 70 PB13, 71 PB14, 72 PB15, 73 PD8, 74 PD9, 75 PD10, 76 PD11, 77 PD12, 78 PD13, 79 PD14, 80 PD15, 81 PH9, 84 PH10, 85 PH11, 86 PH12, 87 PH13, 90 PH14, 91 PH15, 92 PI0, 93 PI1, 96 PI2, 97 PI3, 98 PC6, 99 PC7, 100 PC8, 101 PC9, 102 PA8, 103 PA9, 104 PA10, 105 PA11, 106 PA12, 107 PA13, 111 PA14, 112 PA15, 113 PC10, 114 PC11, 115 PC12, 116 PD0, 117 PD1, 118 PD2, 119 PD3, 120 PD4, 121 PD5, 123 PD6, 124 PD7, 125 PG9, 126 PG10, 127 PG12, 128 PG13, 129 PG14, 132 PG15, 133 PB3, 134 PB4, 135 PB5, 136 PB6, 137 PB7, 138 PH3_BOOT0, 139 PB8, 140 PB9, 141 PE0
part B pins: 6 VBAT, 13 VDDDSI, 14 VDD11DSI_1, 17 VSSDSI_1, 20 VDD11DSI_2, 23 VSSDSI_2, 24 VSS_1, 25 VDD_1, 33 VSSA, 34 VREF+VREFBUF_OUT, 35 VDDA, 40 VSS_2, 41 VDD_2, 54 VSS_3, 55 VDD_3, 64 VLXSMPS, 65 VDDSMPS, 66 VSSSMPS, 67 VDD11_1, 68 VSS_4, 69 VDD_4, 82 VSS_5, 83 VDD_5, 88 VSS_6, 89 VDD_6, 94 VSS_7, 95 VDD_7, 108 VDDUSB, 109 VDD_8, 110 VSS_8, 122 VDD_9, 130 VSS_9, 131 VDDIO2, 142 VDD11_2, 143 VSS_10, 144 VDD_10

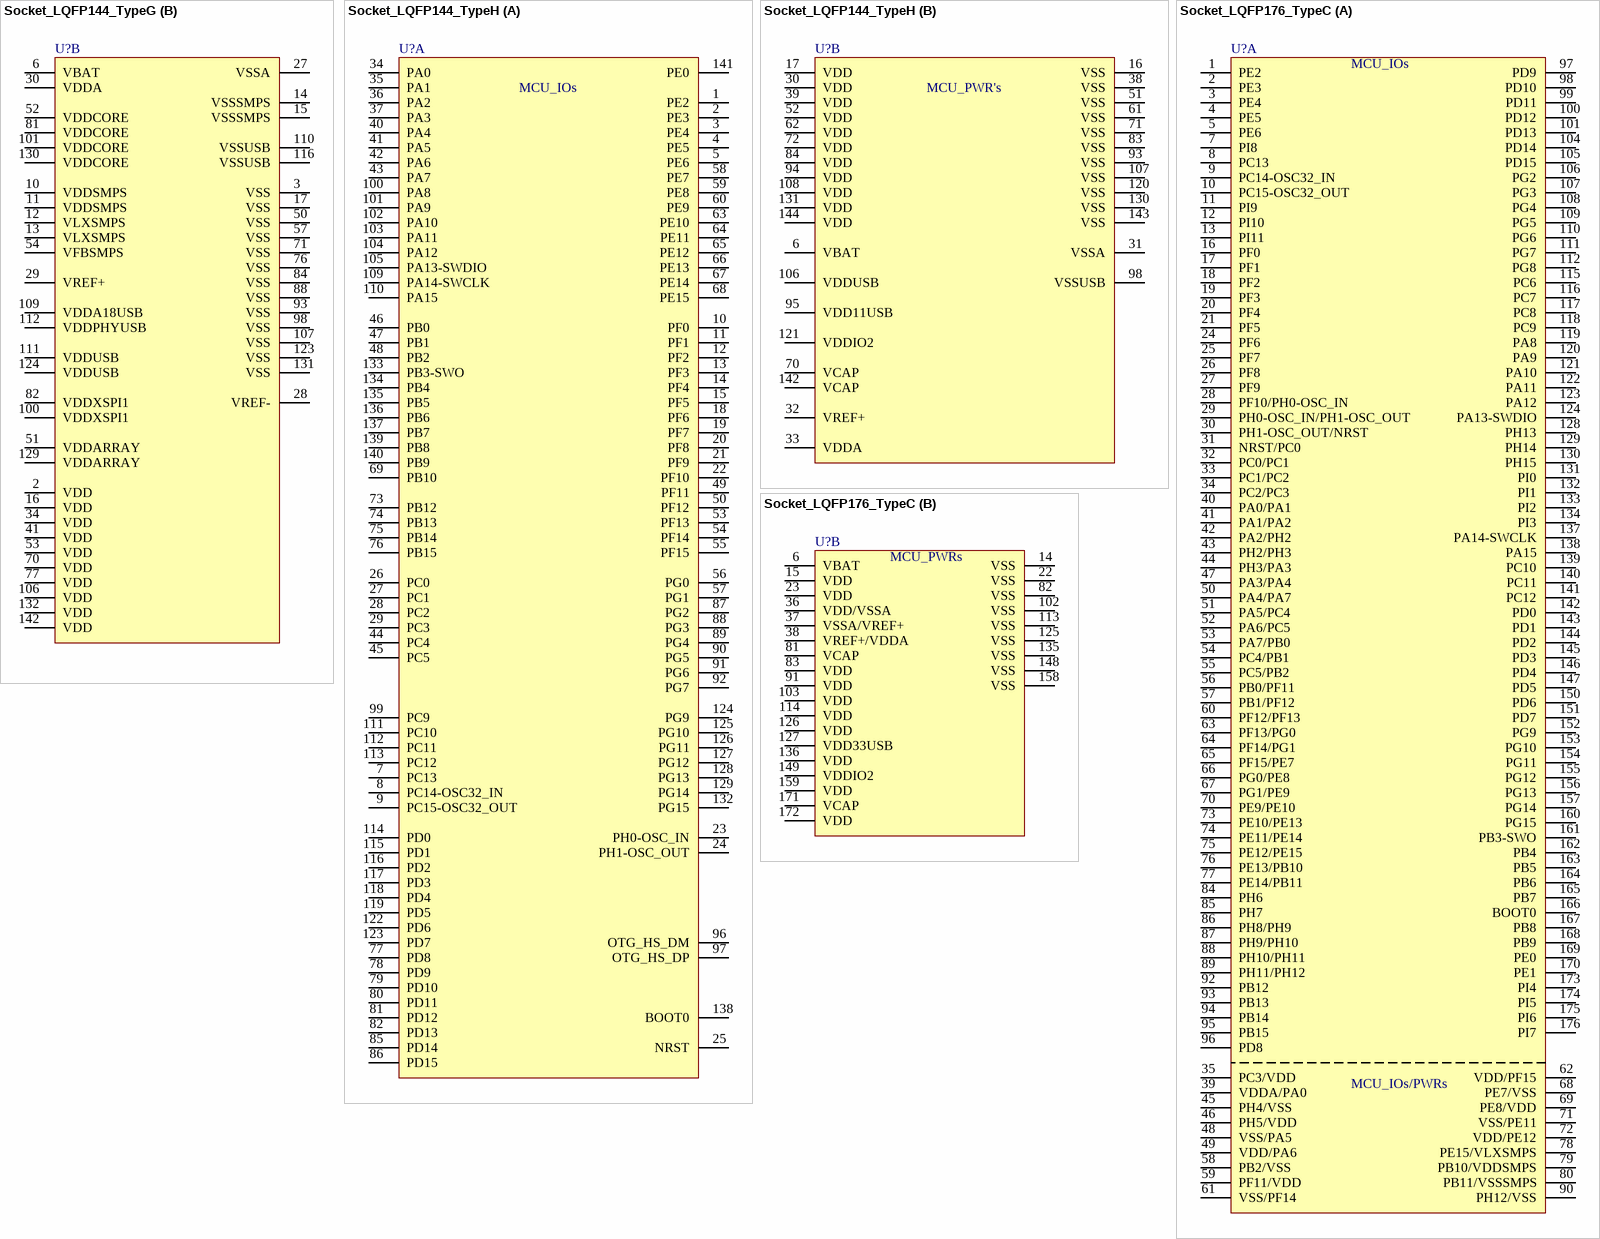
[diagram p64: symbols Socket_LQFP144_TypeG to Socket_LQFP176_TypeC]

## Socket_LQFP144_TypeG
designator U?
part A pins: 1 NRST, 4 PC14-OSC32_IN, 5 PC15-OSC32_OUT, 7 PH0-OSC_IN, 8 PH1-OSC_OUT, 9 PC13, 18 PC9, 19 PC10, 20 PC11, 21 PA0, 22 PA1, 23 PA2, 24 PB12, 25 PB13, 26 PB14, 31 PB15, 32 PC6, 33 PC7, 35 PC8, 36 PD8, 37 PD9, 38 PA3, 39 PA4, 40 PA5, 42 PD10, 43 PA6, 44 PC12, 45 PB0, 46 PB1, 47 PB2, 48 PB3-SWO, 49 PB4, 55 PJ3, 56 PJ4, 58 PJ5, 59 PJ1, 60 PJ2, 61 PJ0, 62 PA8, 63 PB6, 64 PB7, 65 PC0, 66 PC1, 67 PC5, 68 PA9, 69 PA10, 72 PC2, 73 PC3, 74 PA7, 75 PC4, 78 PB5, 79 PB8, 80 PB9, 83 PK4, 85 PI4, 86 PI2, 87 PI3, 89 PK2, 90 PK1, 91 PI5, 92 PI0, 94 PI6, 95 PK3, 96 PI7, 97 PI1, 99 PK0, 102 PD0, 103 PD1, 104 PD2, 105 PD3, 108 PD4, 113 OTG1_TXRTUNE, 114 OTG1_HSDM, 115 OTG1_HSDP, 117 PM8, 118 PM9, 119 PM0, 120 PM1, 121 PM2, 122 PM3, 125 PM4, 126 PM5, 127 PM6, 128 PM7, 133 PA11, 134 PA12, 135 PA13-SWDIO, 136 PA14-SWCLK, 137 PA15, 138 BOOT0, 139 PD5, 140 PD6, 141 PD7, 143 PB10, 144 PB11
part B pins: 2 VDD, 3 VSS, 6 VBAT, 10 VDDSMPS, 11 VDDSMPS, 12 VLXSMPS, 13 VLXSMPS, 14 VSSSMPS, 15 VSSSMPS, 16 VDD, 17 VSS, 27 VSSA, 28 VREF-, 29 VREF+, 30 VDDA, 34 VDD, 41 VDD, 50 VSS, 51 VDDARRAY, 52 VDDCORE, 53 VDD, 54 VFBSMPS, 57 VSS, 70 VDD, 71 VSS, 76 VSS, 77 VDD, 81 VDDCORE, 82 VDDXSPI1, 84 VSS, 88 VSS, 93 VSS, 98 VSS, 100 VDDXSPI1, 101 VDDCORE, 106 VDD, 107 VSS, 109 VDDA18USB, 110 VSSUSB, 111 VDDUSB, 112 VDDPHYUSB, 116 VSSUSB, 123 VSS, 124 VDDUSB, 129 VDDARRAY, 130 VDDCORE, 131 VSS, 132 VDD, 142 VDD

## Socket_LQFP144_TypeH
designator U?
part A pins: 1 PE2, 2 PE3, 3 PE4, 4 PE5, 5 PE6, 7 PC13, 8 PC14-OSC32_IN, 9 PC15-OSC32_OUT, 10 PF0, 11 PF1, 12 PF2, 13 PF3, 14 PF4, 15 PF5, 18 PF6, 19 PF7, 20 PF8, 21 PF9, 22 PF10, 23 PH0-OSC_IN, 24 PH1-OSC_OUT, 25 NRST, 26 PC0, 27 PC1, 28 PC2, 29 PC3, 34 PA0, 35 PA1, 36 PA2, 37 PA3, 40 PA4, 41 PA5, 42 PA6, 43 PA7, 44 PC4, 45 PC5, 46 PB0, 47 PB1, 48 PB2, 49 PF11, 50 PF12, 53 PF13, 54 PF14, 55 PF15, 56 PG0, 57 PG1, 58 PE7, 59 PE8, 60 PE9, 63 PE10, 64 PE11, 65 PE12, 66 PE13, 67 PE14, 68 PE15, 69 PB10, 73 PB12, 74 PB13, 75 PB14, 76 PB15, 77 PD8, 78 PD9, 79 PD10, 80 PD11, 81 PD12, 82 PD13, 85 PD14, 86 PD15, 87 PG2, 88 PG3, 89 PG4, 90 PG5, 91 PG6, 92 PG7, 96 OTG_HS_DM, 97 OTG_HS_DP, 99 PC9, 100 PA8, 101 PA9, 102 PA10, 103 PA11, 104 PA12, 105 PA13-SWDIO, 109 PA14-SWCLK, 110 PA15, 111 PC10, 112 PC11, 113 PC12, 114 PD0, 115 PD1, 116 PD2, 117 PD3, 118 PD4, 119 PD5, 122 PD6, 123 PD7, 124 PG9, 125 PG10, 126 PG11, 127 PG12, 128 PG13, 129 PG14, 132 PG15, 133 PB3-SWO, 134 PB4, 135 PB5, 136 PB6, 137 PB7, 138 BOOT0, 139 PB8, 140 PB9, 141 PE0
part B pins: 6 VBAT, 16 VSS, 17 VDD, 30 VDD, 31 VSSA, 32 VREF+, 33 VDDA, 38 VSS, 39 VDD, 51 VSS, 52 VDD, 61 VSS, 62 VDD, 70 VCAP, 71 VSS, 72 VDD, 83 VSS, 84 VDD, 93 VSS, 94 VDD, 95 VDD11USB, 98 VSSUSB, 106 VDDUSB, 107 VSS, 108 VDD, 120 VSS, 121 VDDIO2, 130 VSS, 131 VDD, 142 VCAP, 143 VSS, 144 VDD

## Socket_LQFP176_TypeC
designator U?
part A pins: 1 PE2, 2 PE3, 3 PE4, 4 PE5, 5 PE6, 7 PI8, 8 PC13, 9 PC14-OSC32_IN, 10 PC15-OSC32_OUT, 11 PI9, 12 PI10, 13 PI11, 16 PF0, 17 PF1, 18 PF2, 19 PF3, 20 PF4, 21 PF5, 24 PF6, 25 PF7, 26 PF8, 27 PF9, 28 PF10/PH0-OSC_IN, 29 PH0-OSC_IN/PH1-OSC_OUT, 30 PH1-OSC_OUT/NRST, 31 NRST/PC0, 32 PC0/PC1, 33 PC1/PC2, 34 PC2/PC3, 35 PC3/VDD, 39 VDDA/PA0, 40 PA0/PA1, 41 PA1/PA2, 42 PA2/PH2, 43 PH2/PH3, 44 PH3/PA3, 45 PH4/VSS, 46 PH5/VDD, 47 PA3/PA4, 48 VSS/PA5, 49 VDD/PA6, 50 PA4/PA7, 51 PA5/PC4, 52 PA6/PC5, 53 PA7/PB0, 54 PC4/PB1, 55 PC5/PB2, 56 PB0/PF11, 57 PB1/PF12, 58 PB2/VSS, 59 PF11/VDD, 60 PF12/PF13, 61 VSS/PF14, 62 VDD/PF15, 63 PF13/PG0, 64 PF14/PG1, 65 PF15/PE7, 66 PG0/PE8, 67 PG1/PE9, 68 PE7/VSS, 69 PE8/VDD, 70 PE9/PE10, 71 VSS/PE11, 72 VDD/PE12, 73 PE10/PE13, 74 PE11/PE14, 75 PE12/PE15, 76 PE13/PB10, 77 PE14/PB11, 78 PE15/VLXSMPS, 79 PB10/VDDSMPS, 80 PB11/VSSSMPS, 84 PH6, 85 PH7, 86 PH8/PH9, 87 PH9/PH10, 88 PH10/PH11, 89 PH11/PH12, 90 PH12/VSS, 92 PB12, 93 PB13, 94 PB14, 95 PB15, 96 PD8, 97 PD9, 98 PD10, 99 PD11, 100 PD12, 101 PD13, 104 PD14, 105 PD15, 106 PG2, 107 PG3, 108 PG4, 109 PG5, 110 PG6, 111 PG7, 112 PG8, 115 PC6, 116 PC7, 117 PC8, 118 PC9, 119 PA8, 120 PA9, 121 PA10, 122 PA11, 123 PA12, 124 PA13-SWDIO, 128 PH13, 129 PH14, 130 PH15, 131 PI0, 132 PI1, 133 PI2, 134 PI3, 137 PA14-SWCLK, 138 PA15, 139 PC10, 140 PC11, 141 PC12, 142 PD0, 143 PD1, 144 PD2, 145 PD3, 146 PD4, 147 PD5, 150 PD6, 151 PD7, 152 PG9, 153 PG10, 154 PG11, 155 PG12, 156 PG13, 157 PG14, 160 PG15, 161 PB3-SWO, 162 PB4, 163 PB5, 164 PB6, 165 PB7, 166 BOOT0, 167 PB8, 168 PB9, 169 PE0, 170 PE1, 173 PI4, 174 PI5, 175 PI6, 176 PI7
part B pins: 6 VBAT, 14 VSS, 15 VDD, 22 VSS, 23 VDD, 36 VDD/VSSA, 37 VSSA/VREF+, 38 VREF+/VDDA, 81 VCAP, 82 VSS, 83 VDD, 91 VDD, 102 VSS, 103 VDD, 113 VSS, 114 VDD, 125 VSS, 126 VDD, 127 VDD33USB, 135 VSS, 136 VDD, 148 VSS, 149 VDDIO2, 158 VSS, 159 VDD, 171 VCAP, 172 VDD

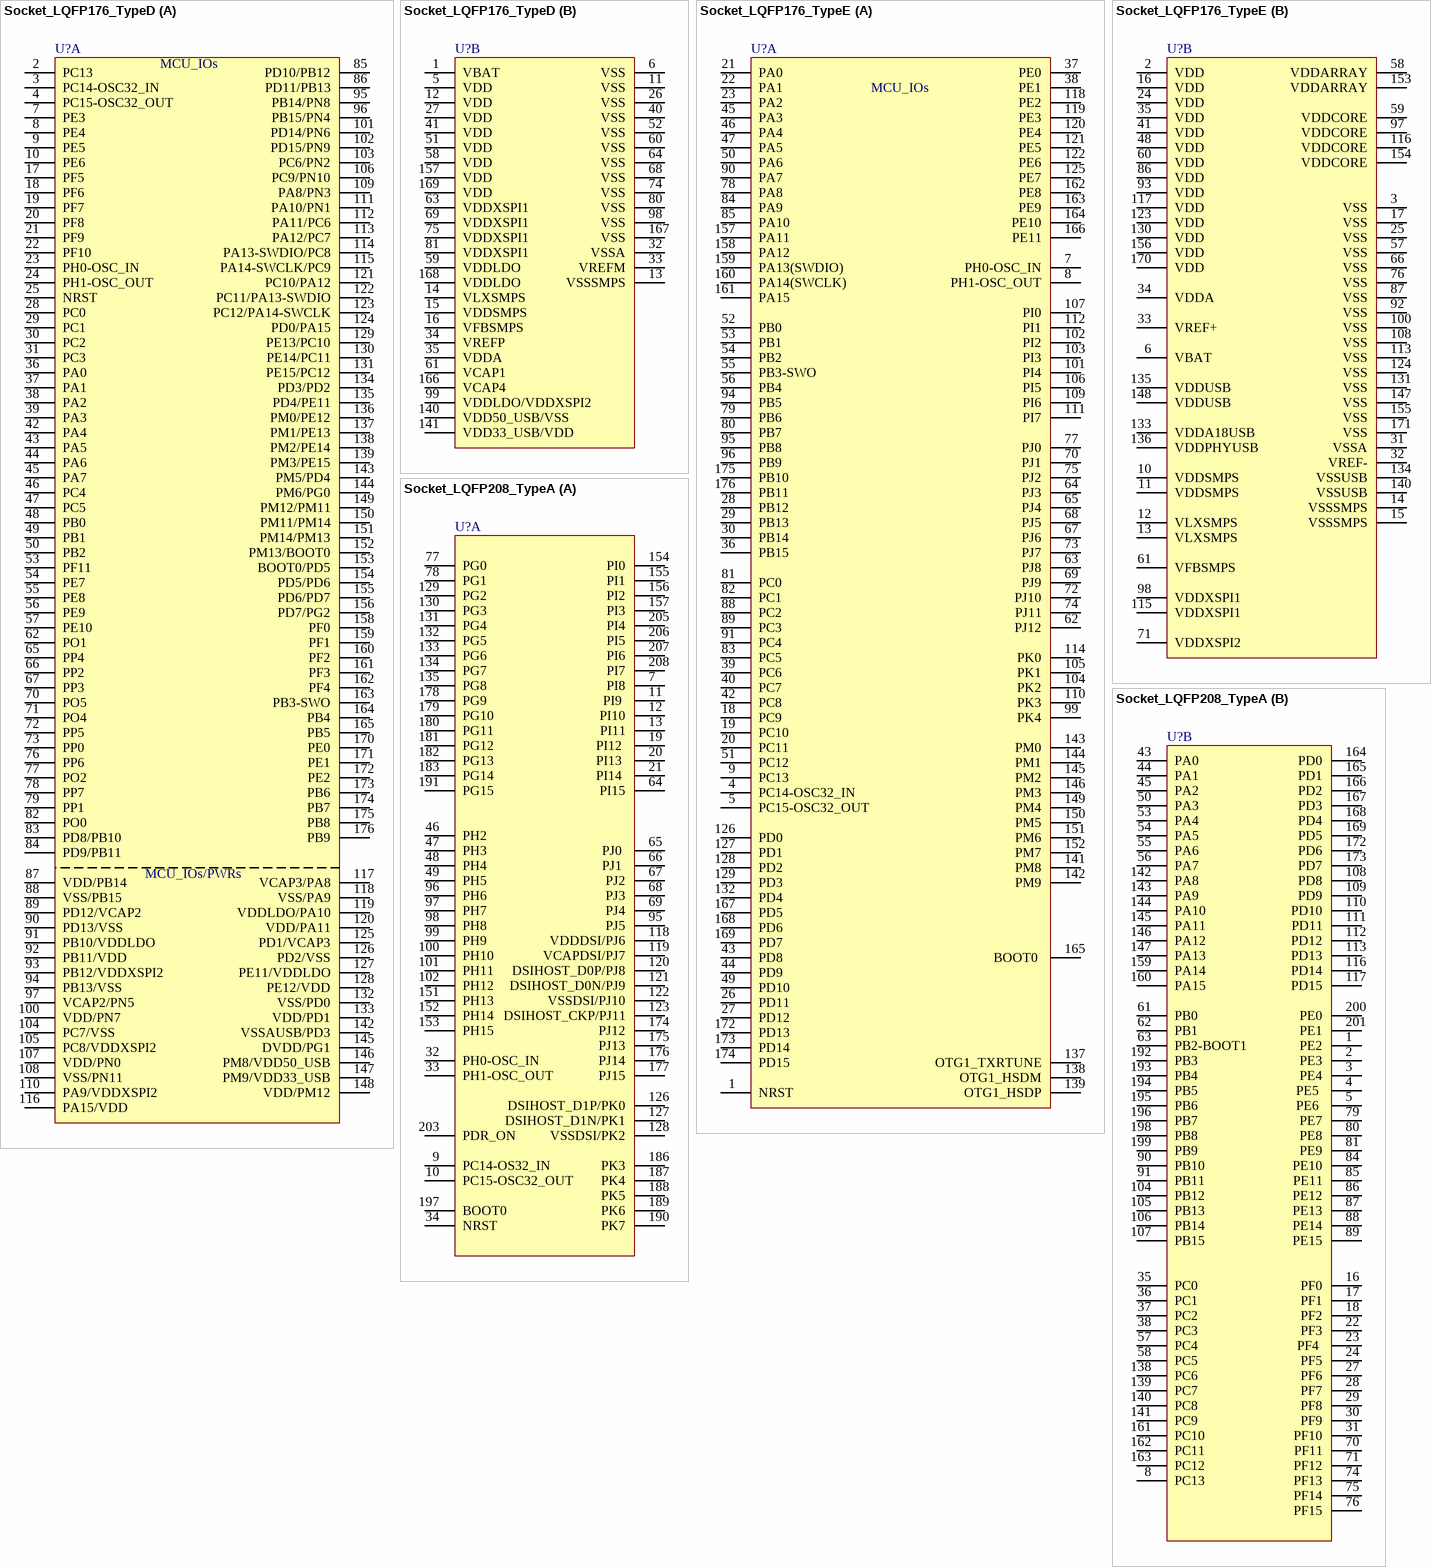
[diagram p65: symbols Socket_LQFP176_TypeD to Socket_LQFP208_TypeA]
